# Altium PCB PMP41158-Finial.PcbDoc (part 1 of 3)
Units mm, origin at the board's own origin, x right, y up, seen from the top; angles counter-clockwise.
Board outline 125.73 x 87.63 mm, 6 copper layers (Top Layer, Layer 2, Layer 3, Layer 4, Layer 5, Bottom Layer), stack 1.999 mm thick; 200 components, 69 nets, 525 pads, 780 vias.
Unrouted connection lines stored in the file: 16.
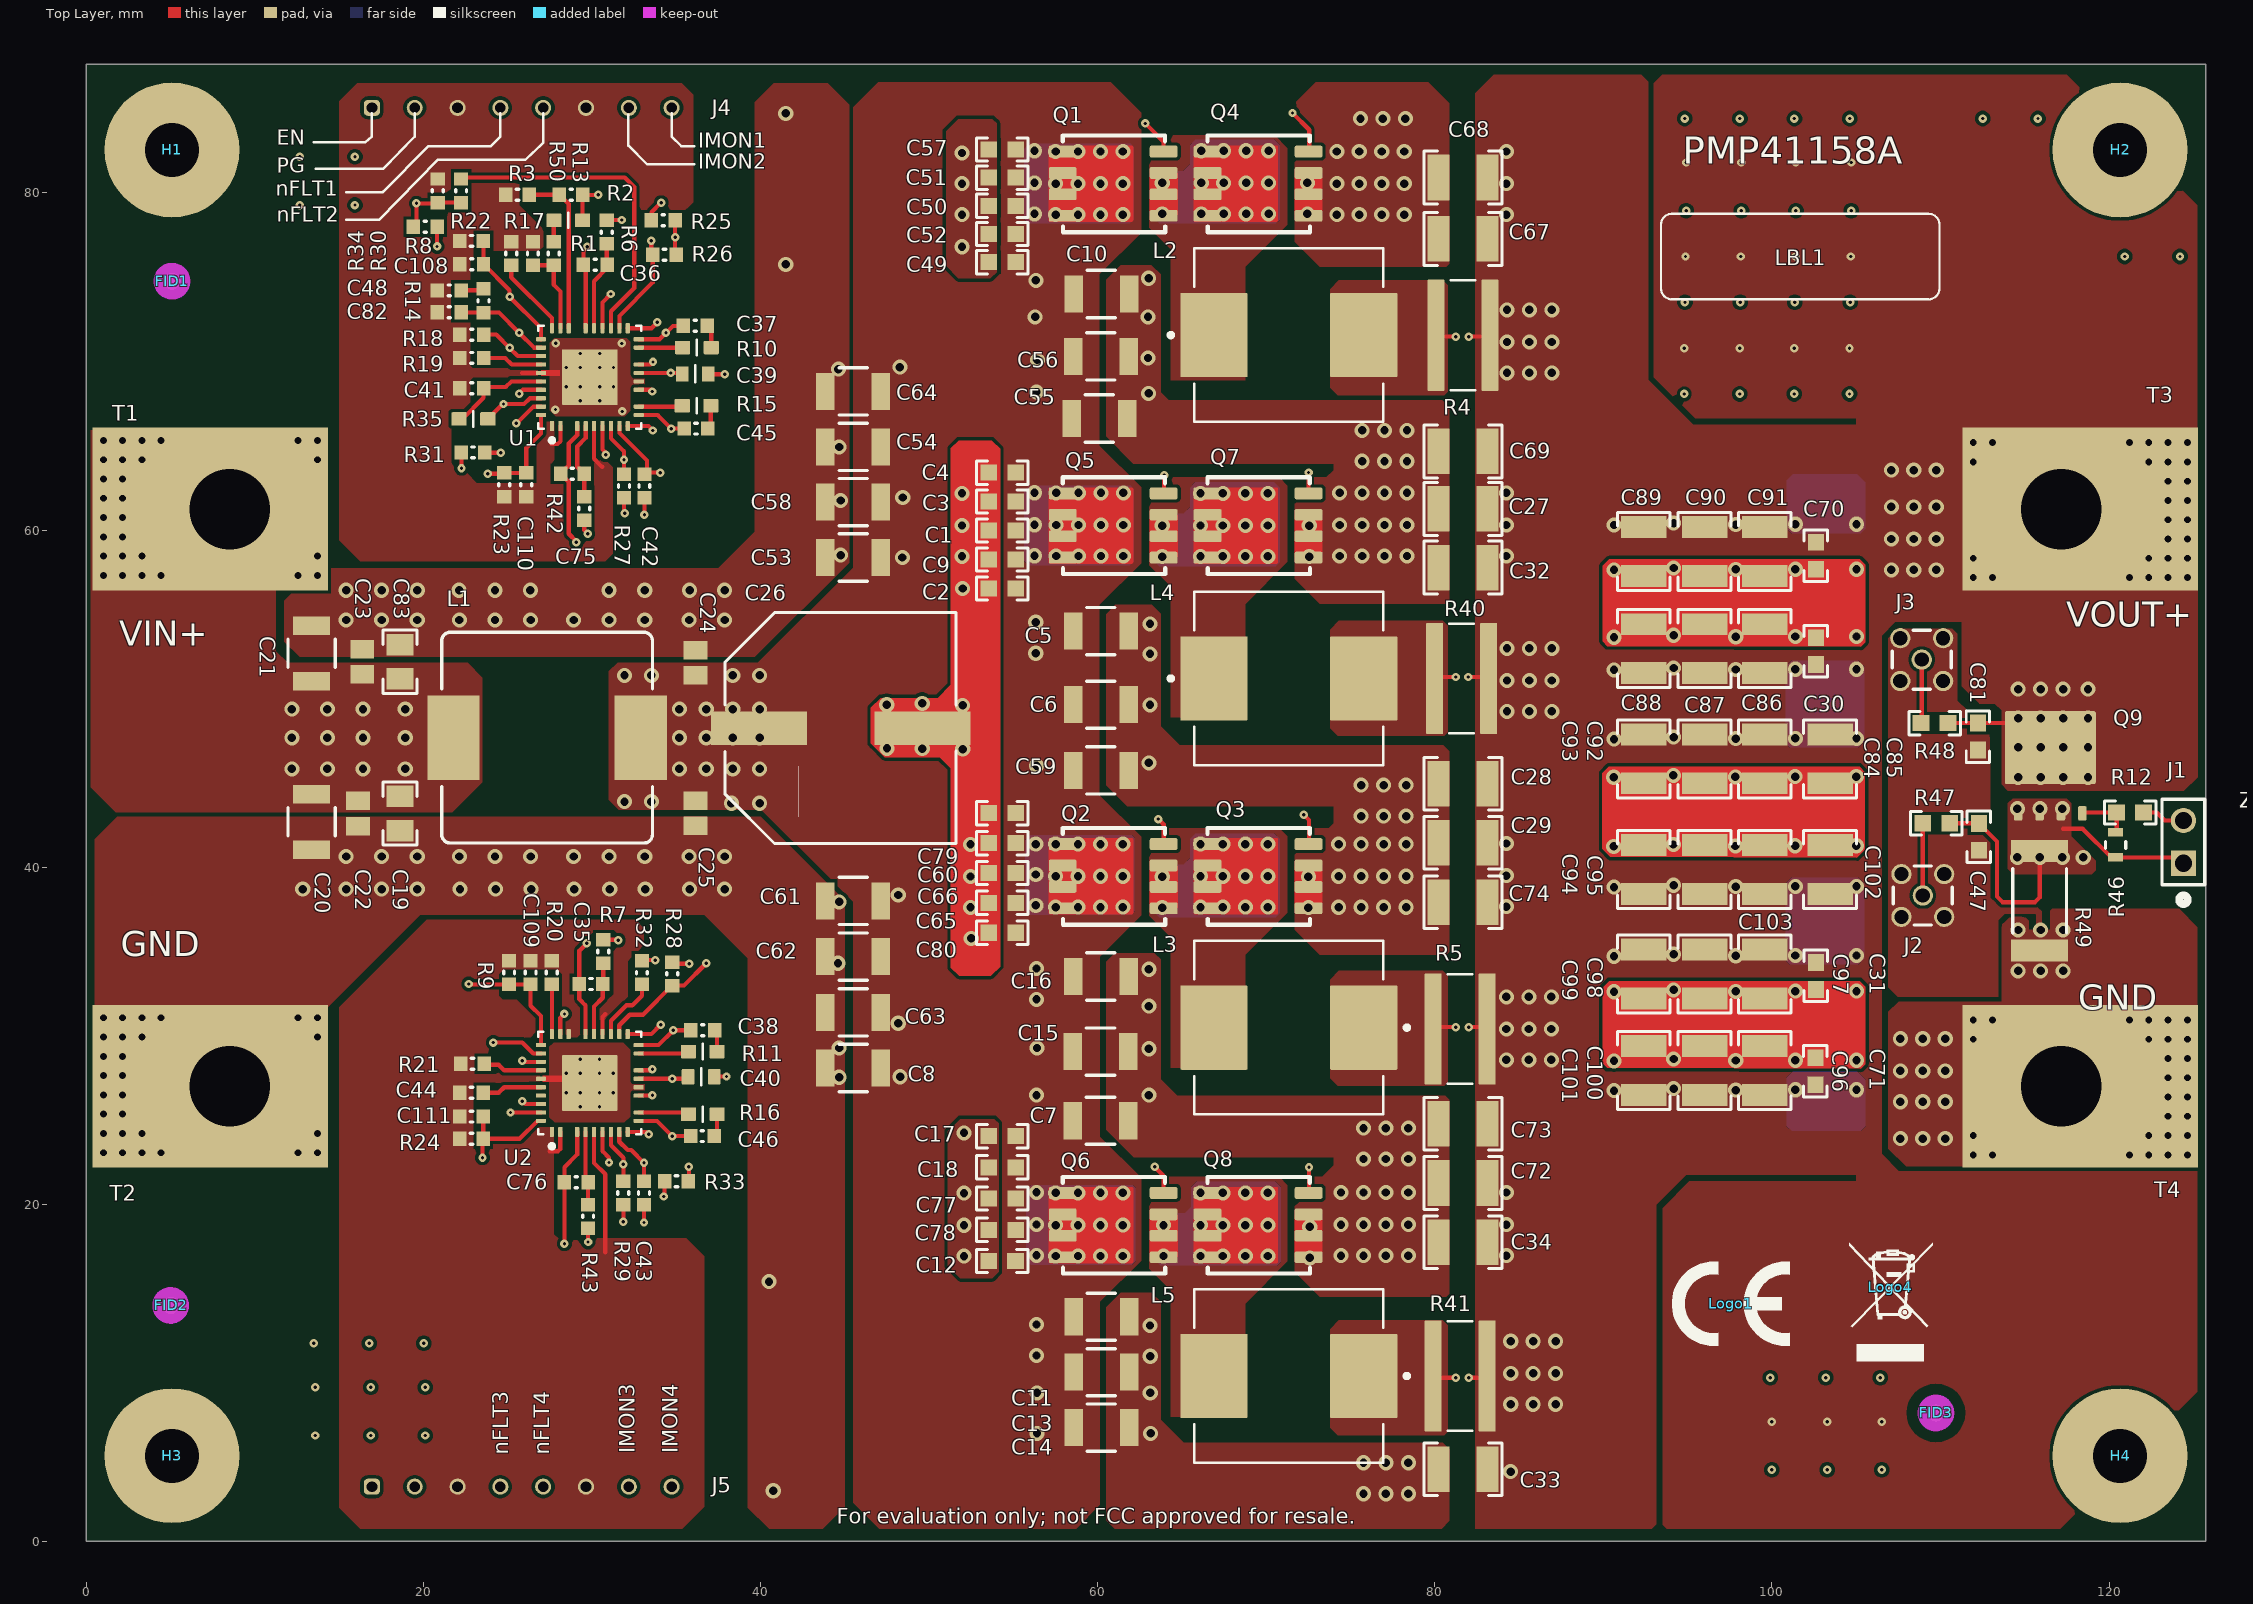
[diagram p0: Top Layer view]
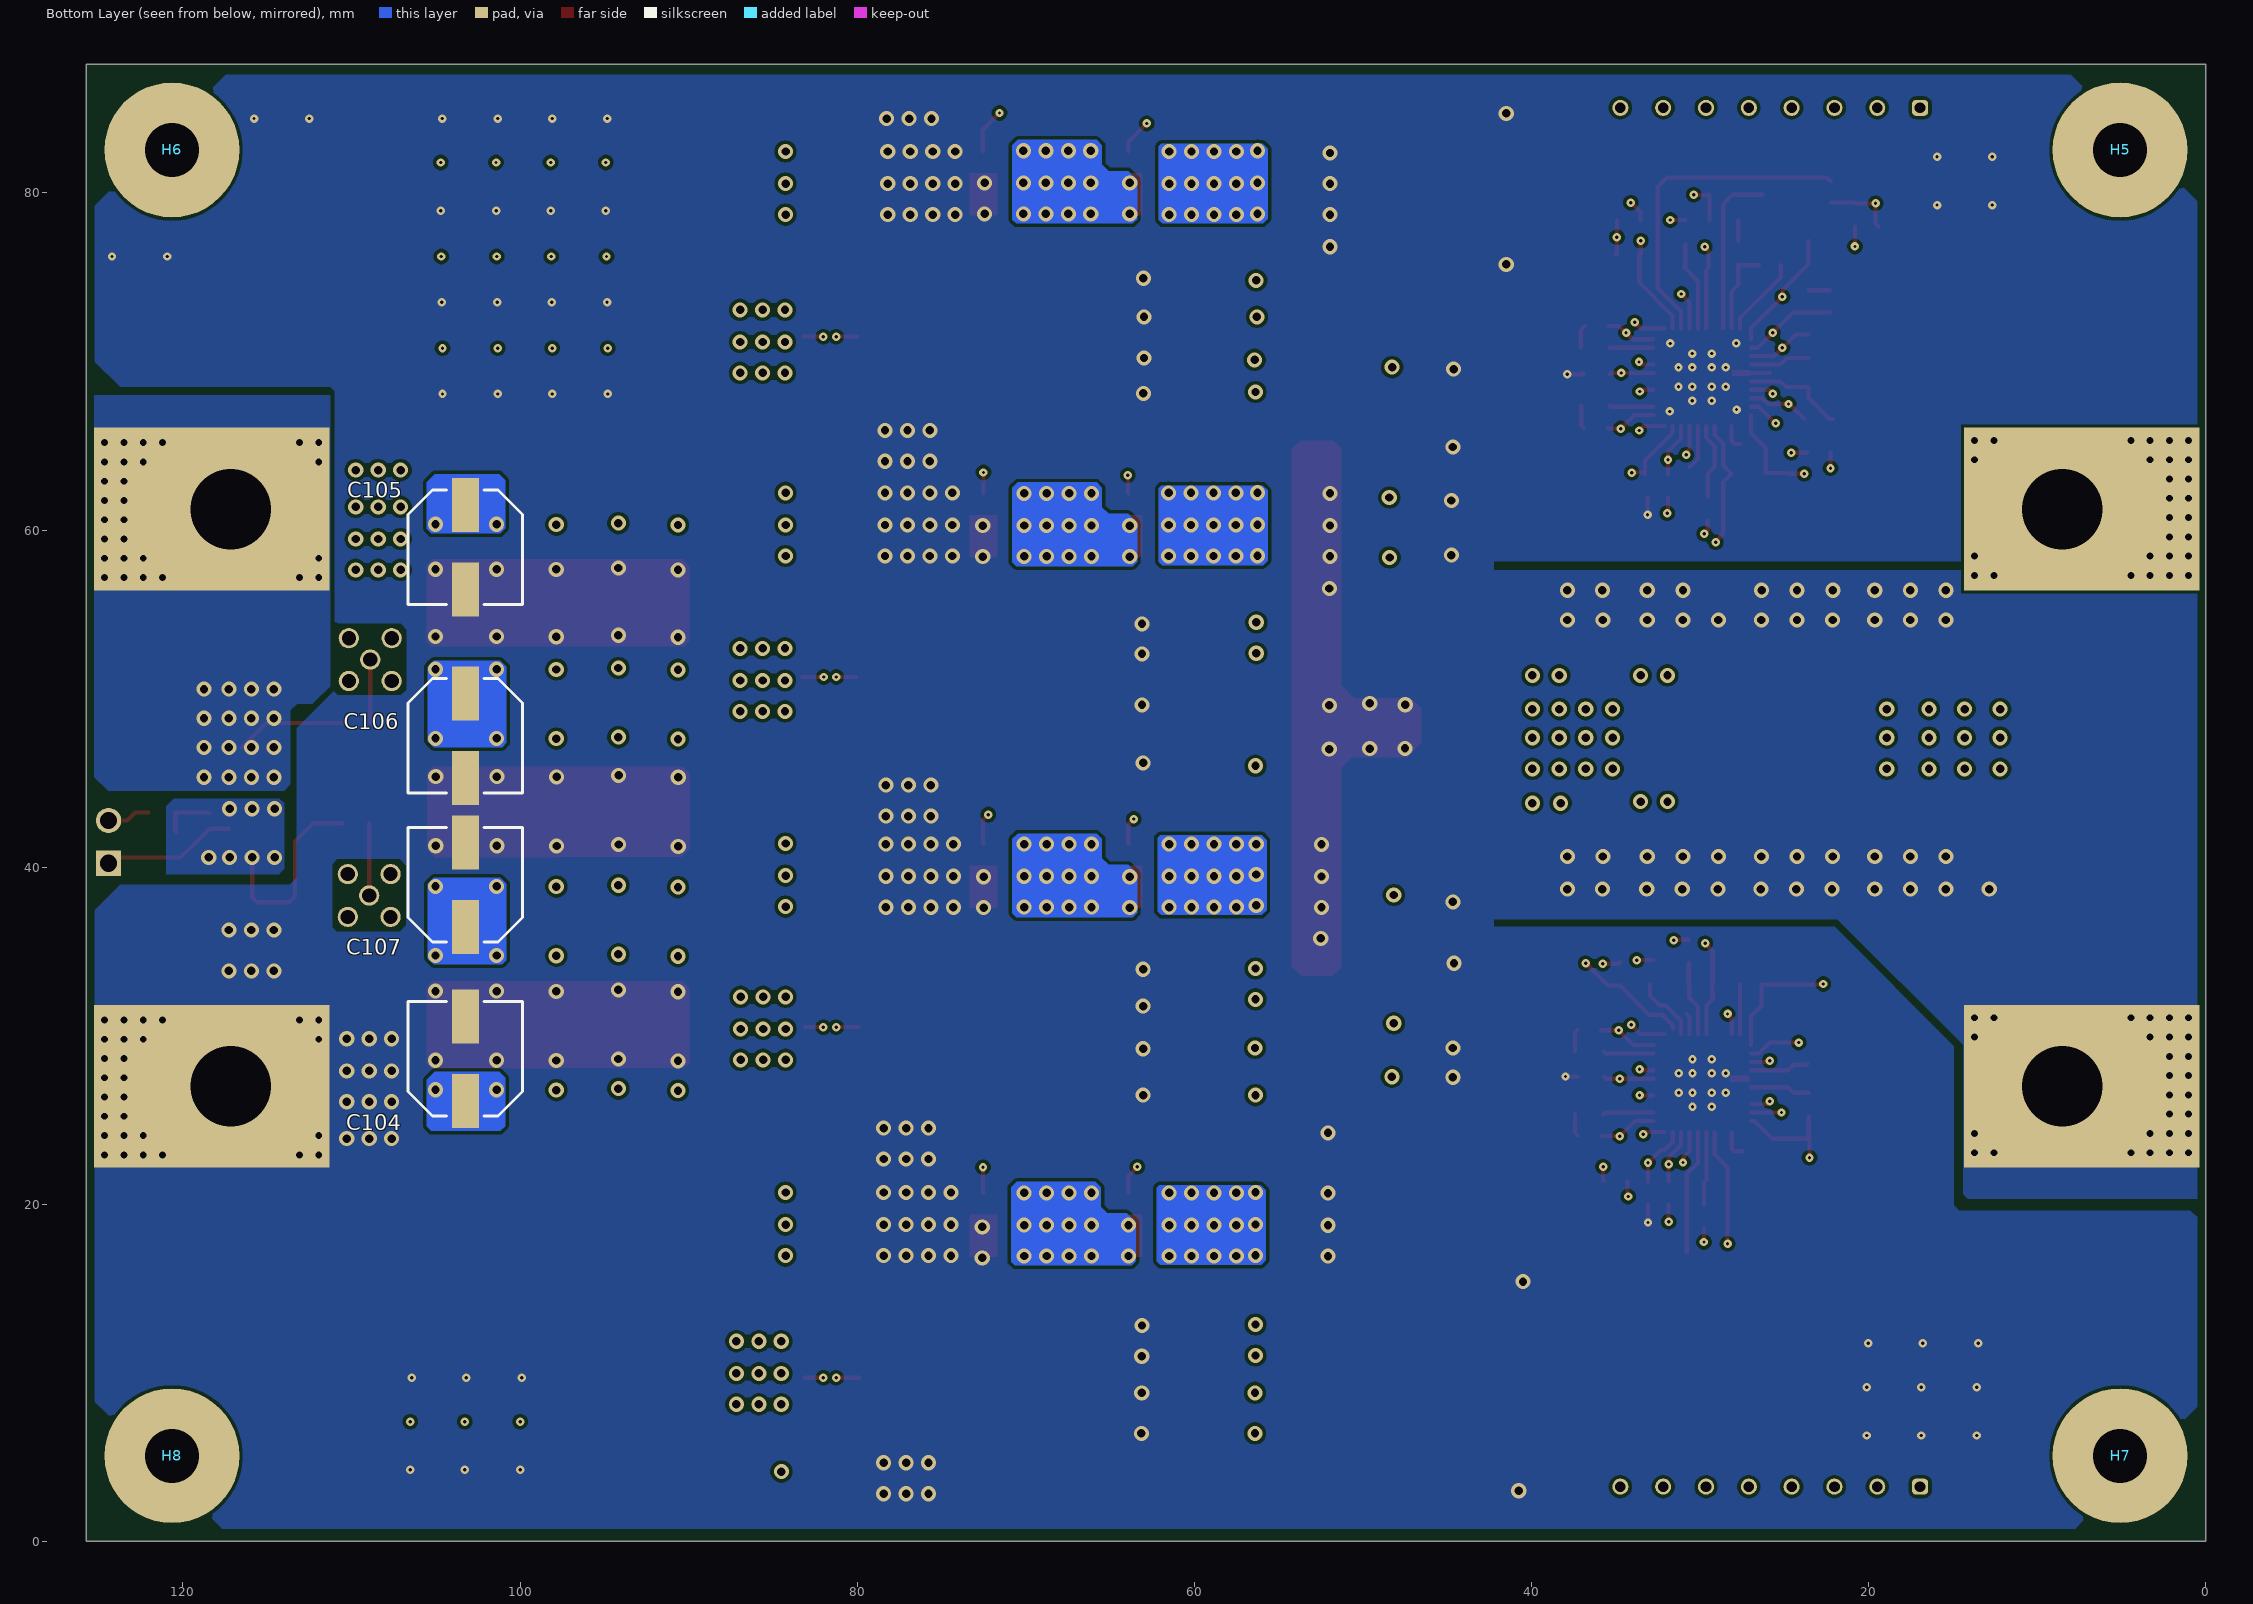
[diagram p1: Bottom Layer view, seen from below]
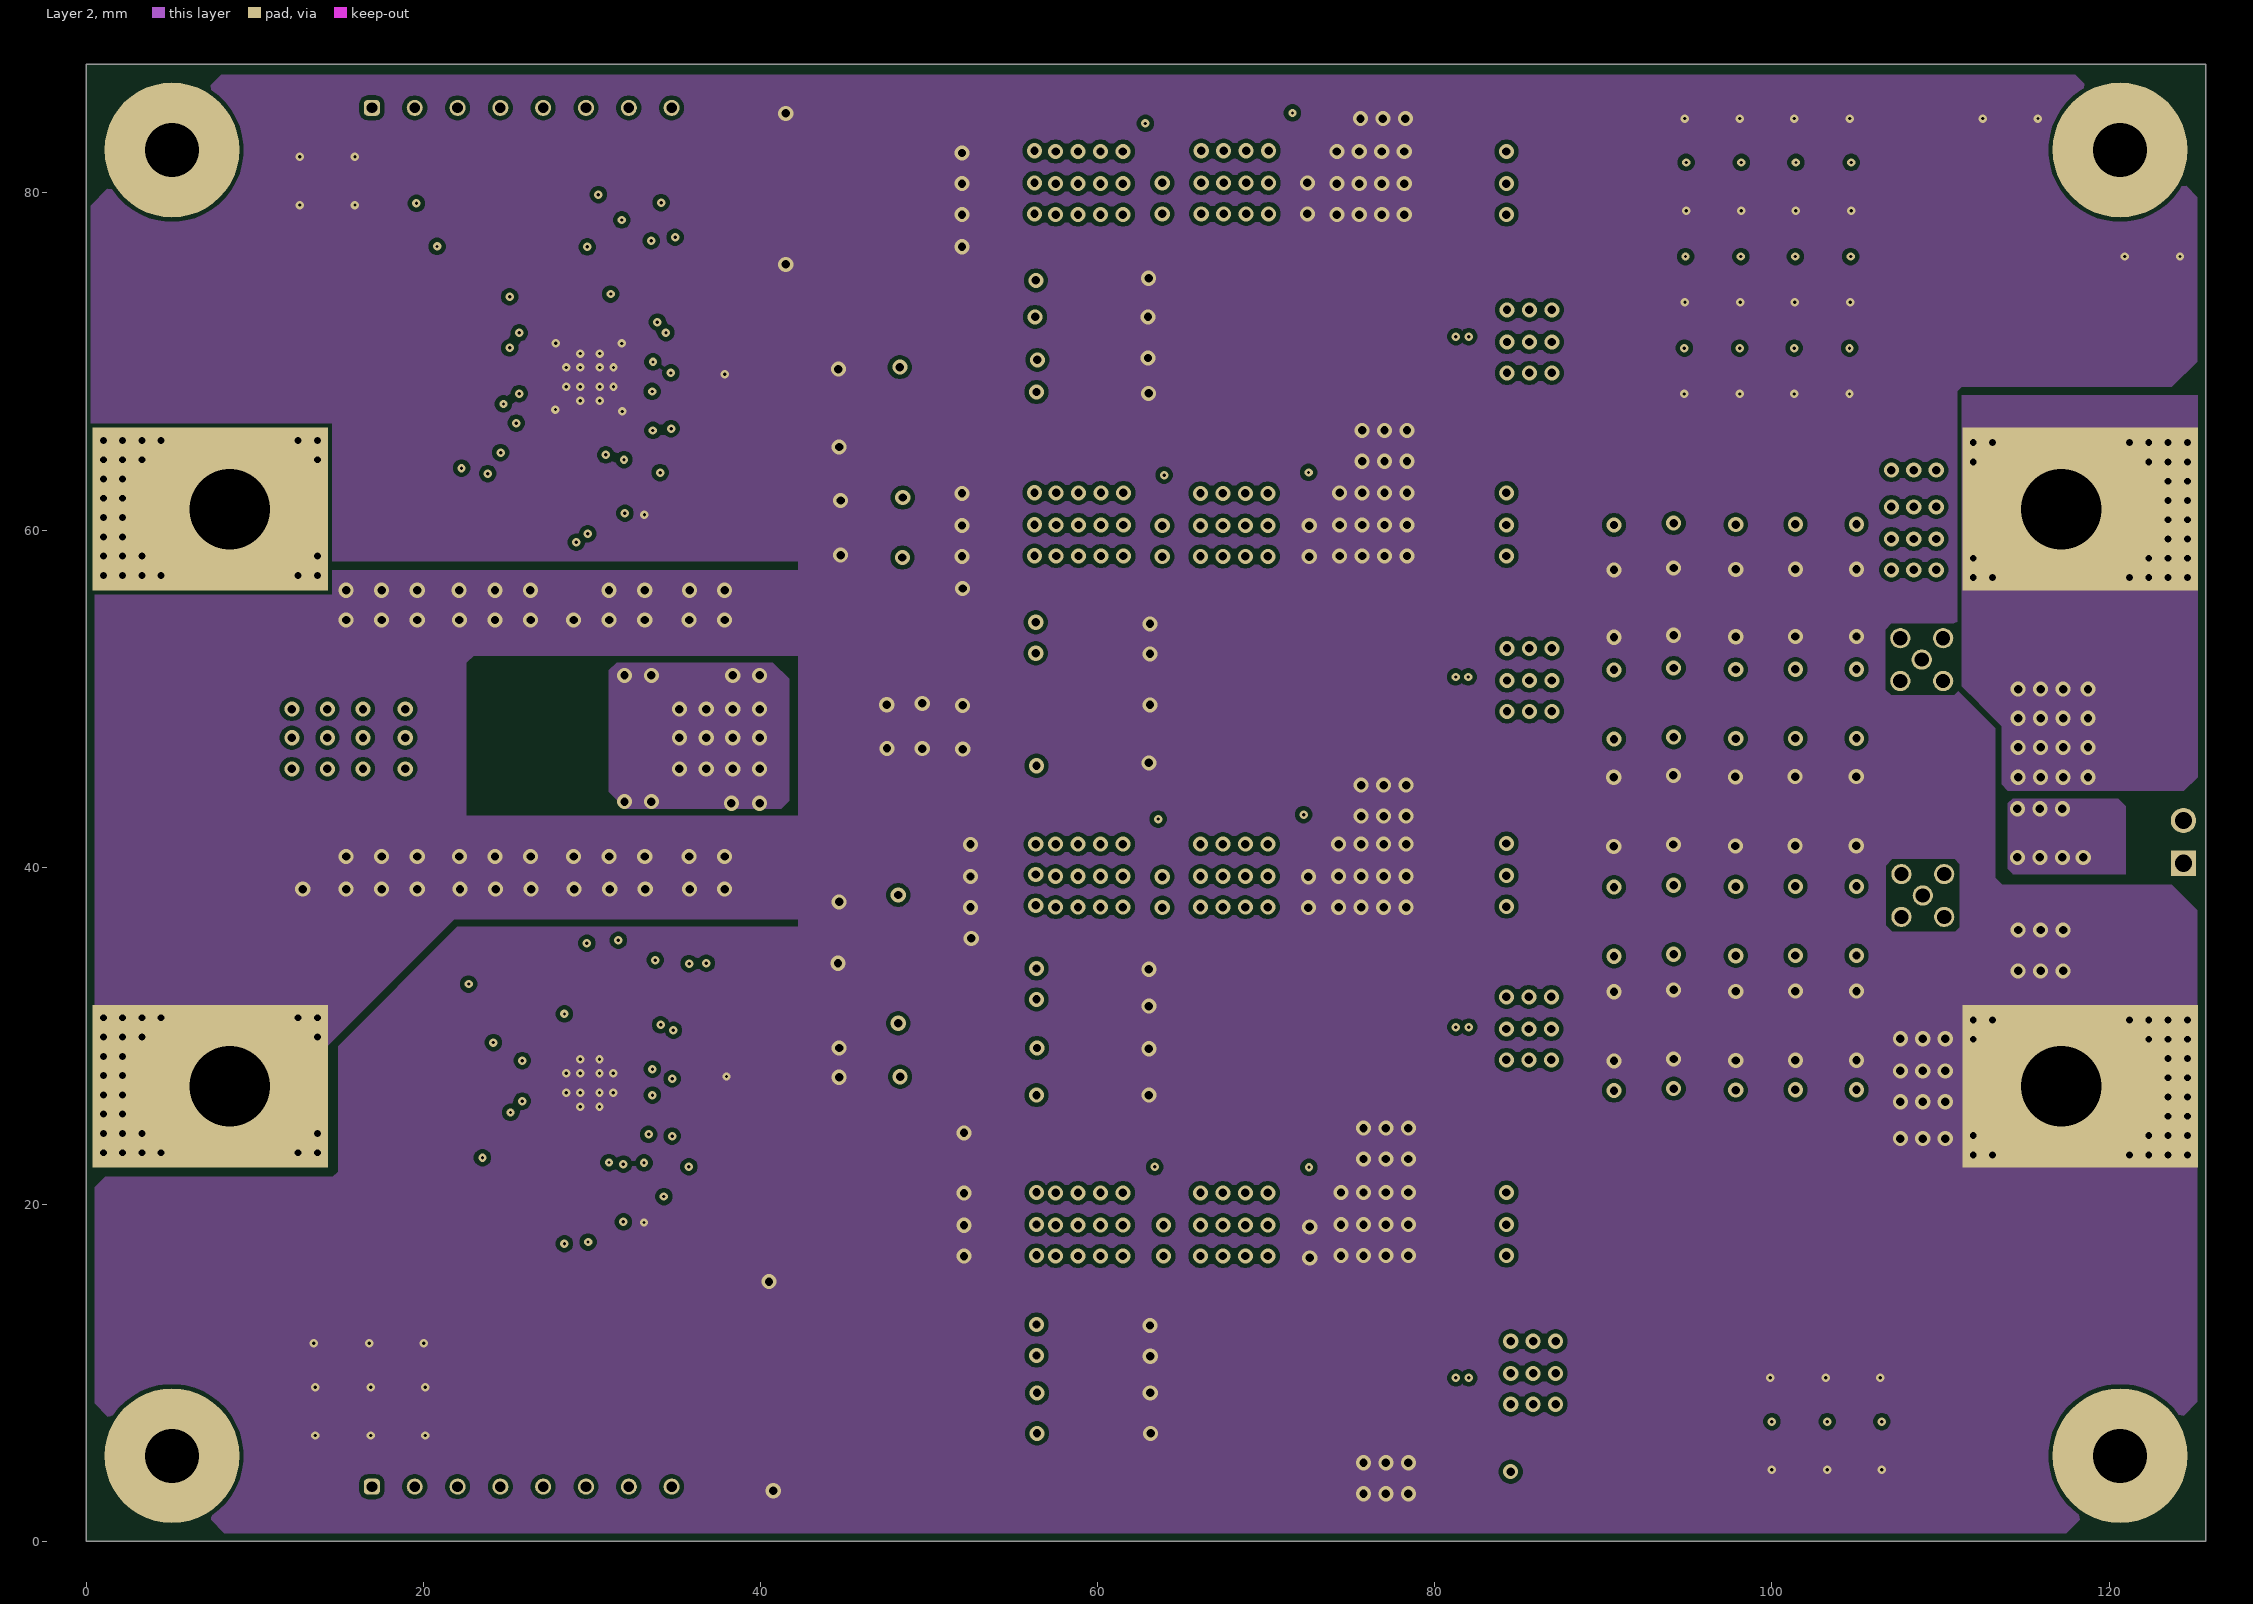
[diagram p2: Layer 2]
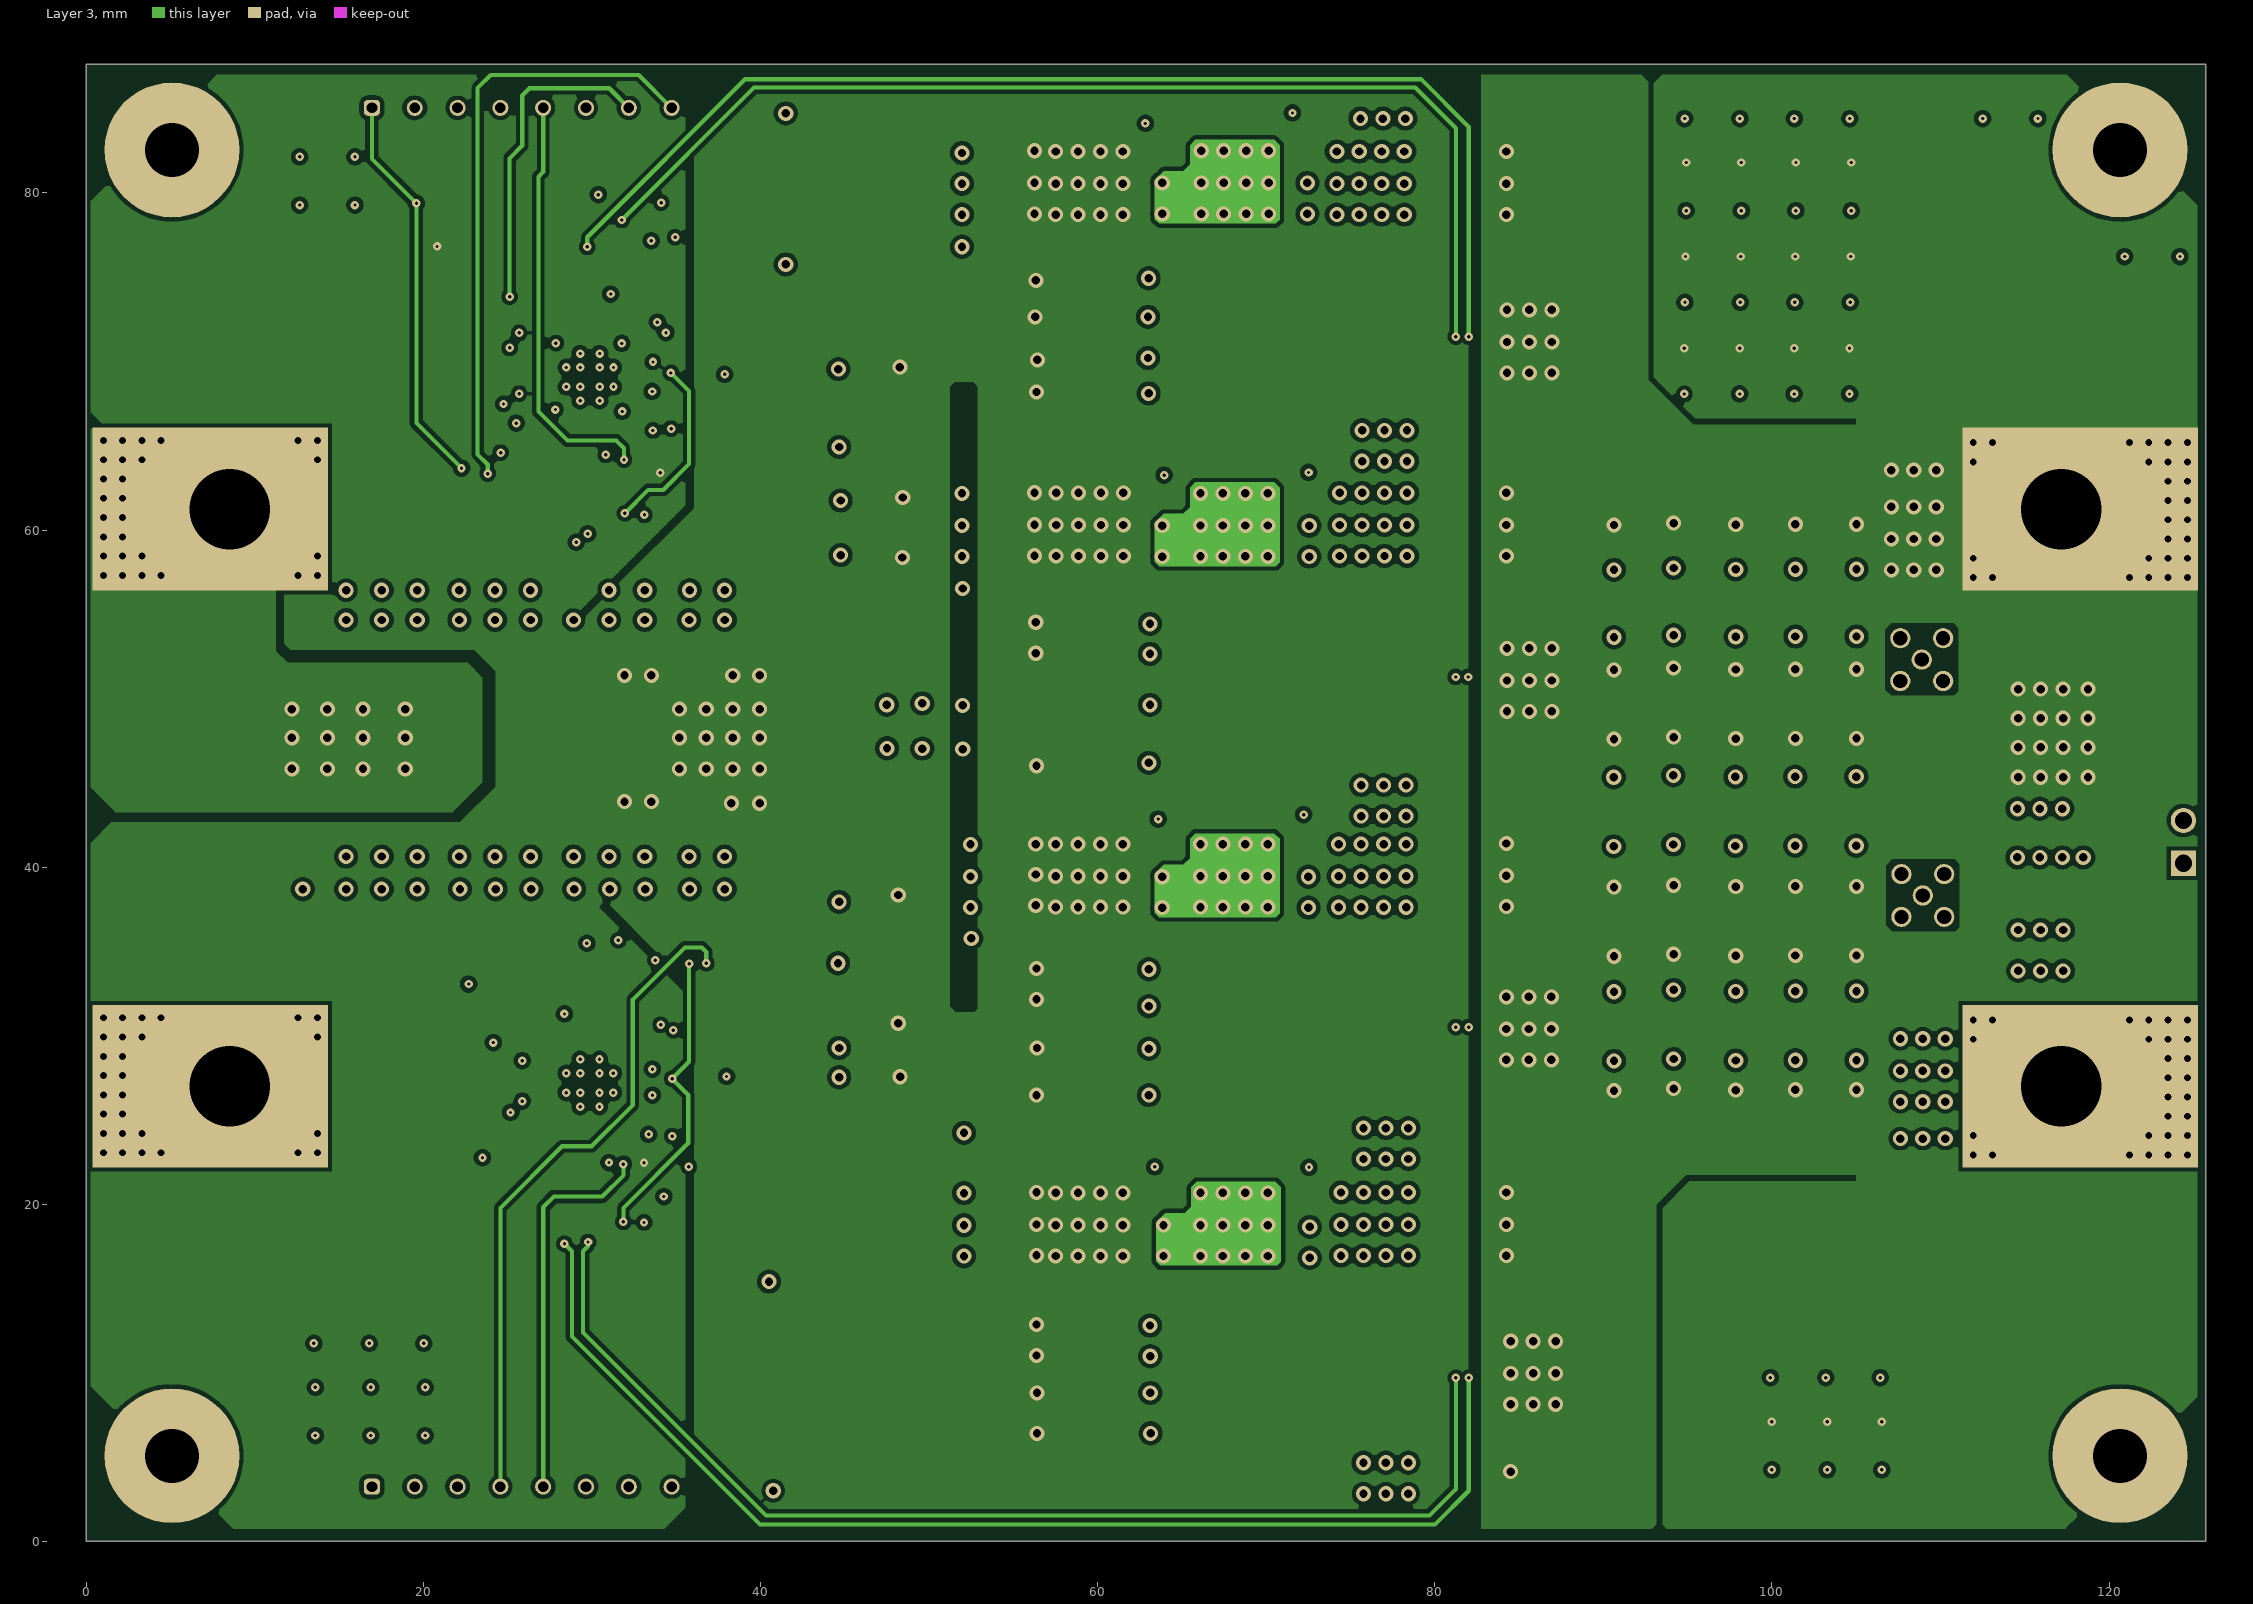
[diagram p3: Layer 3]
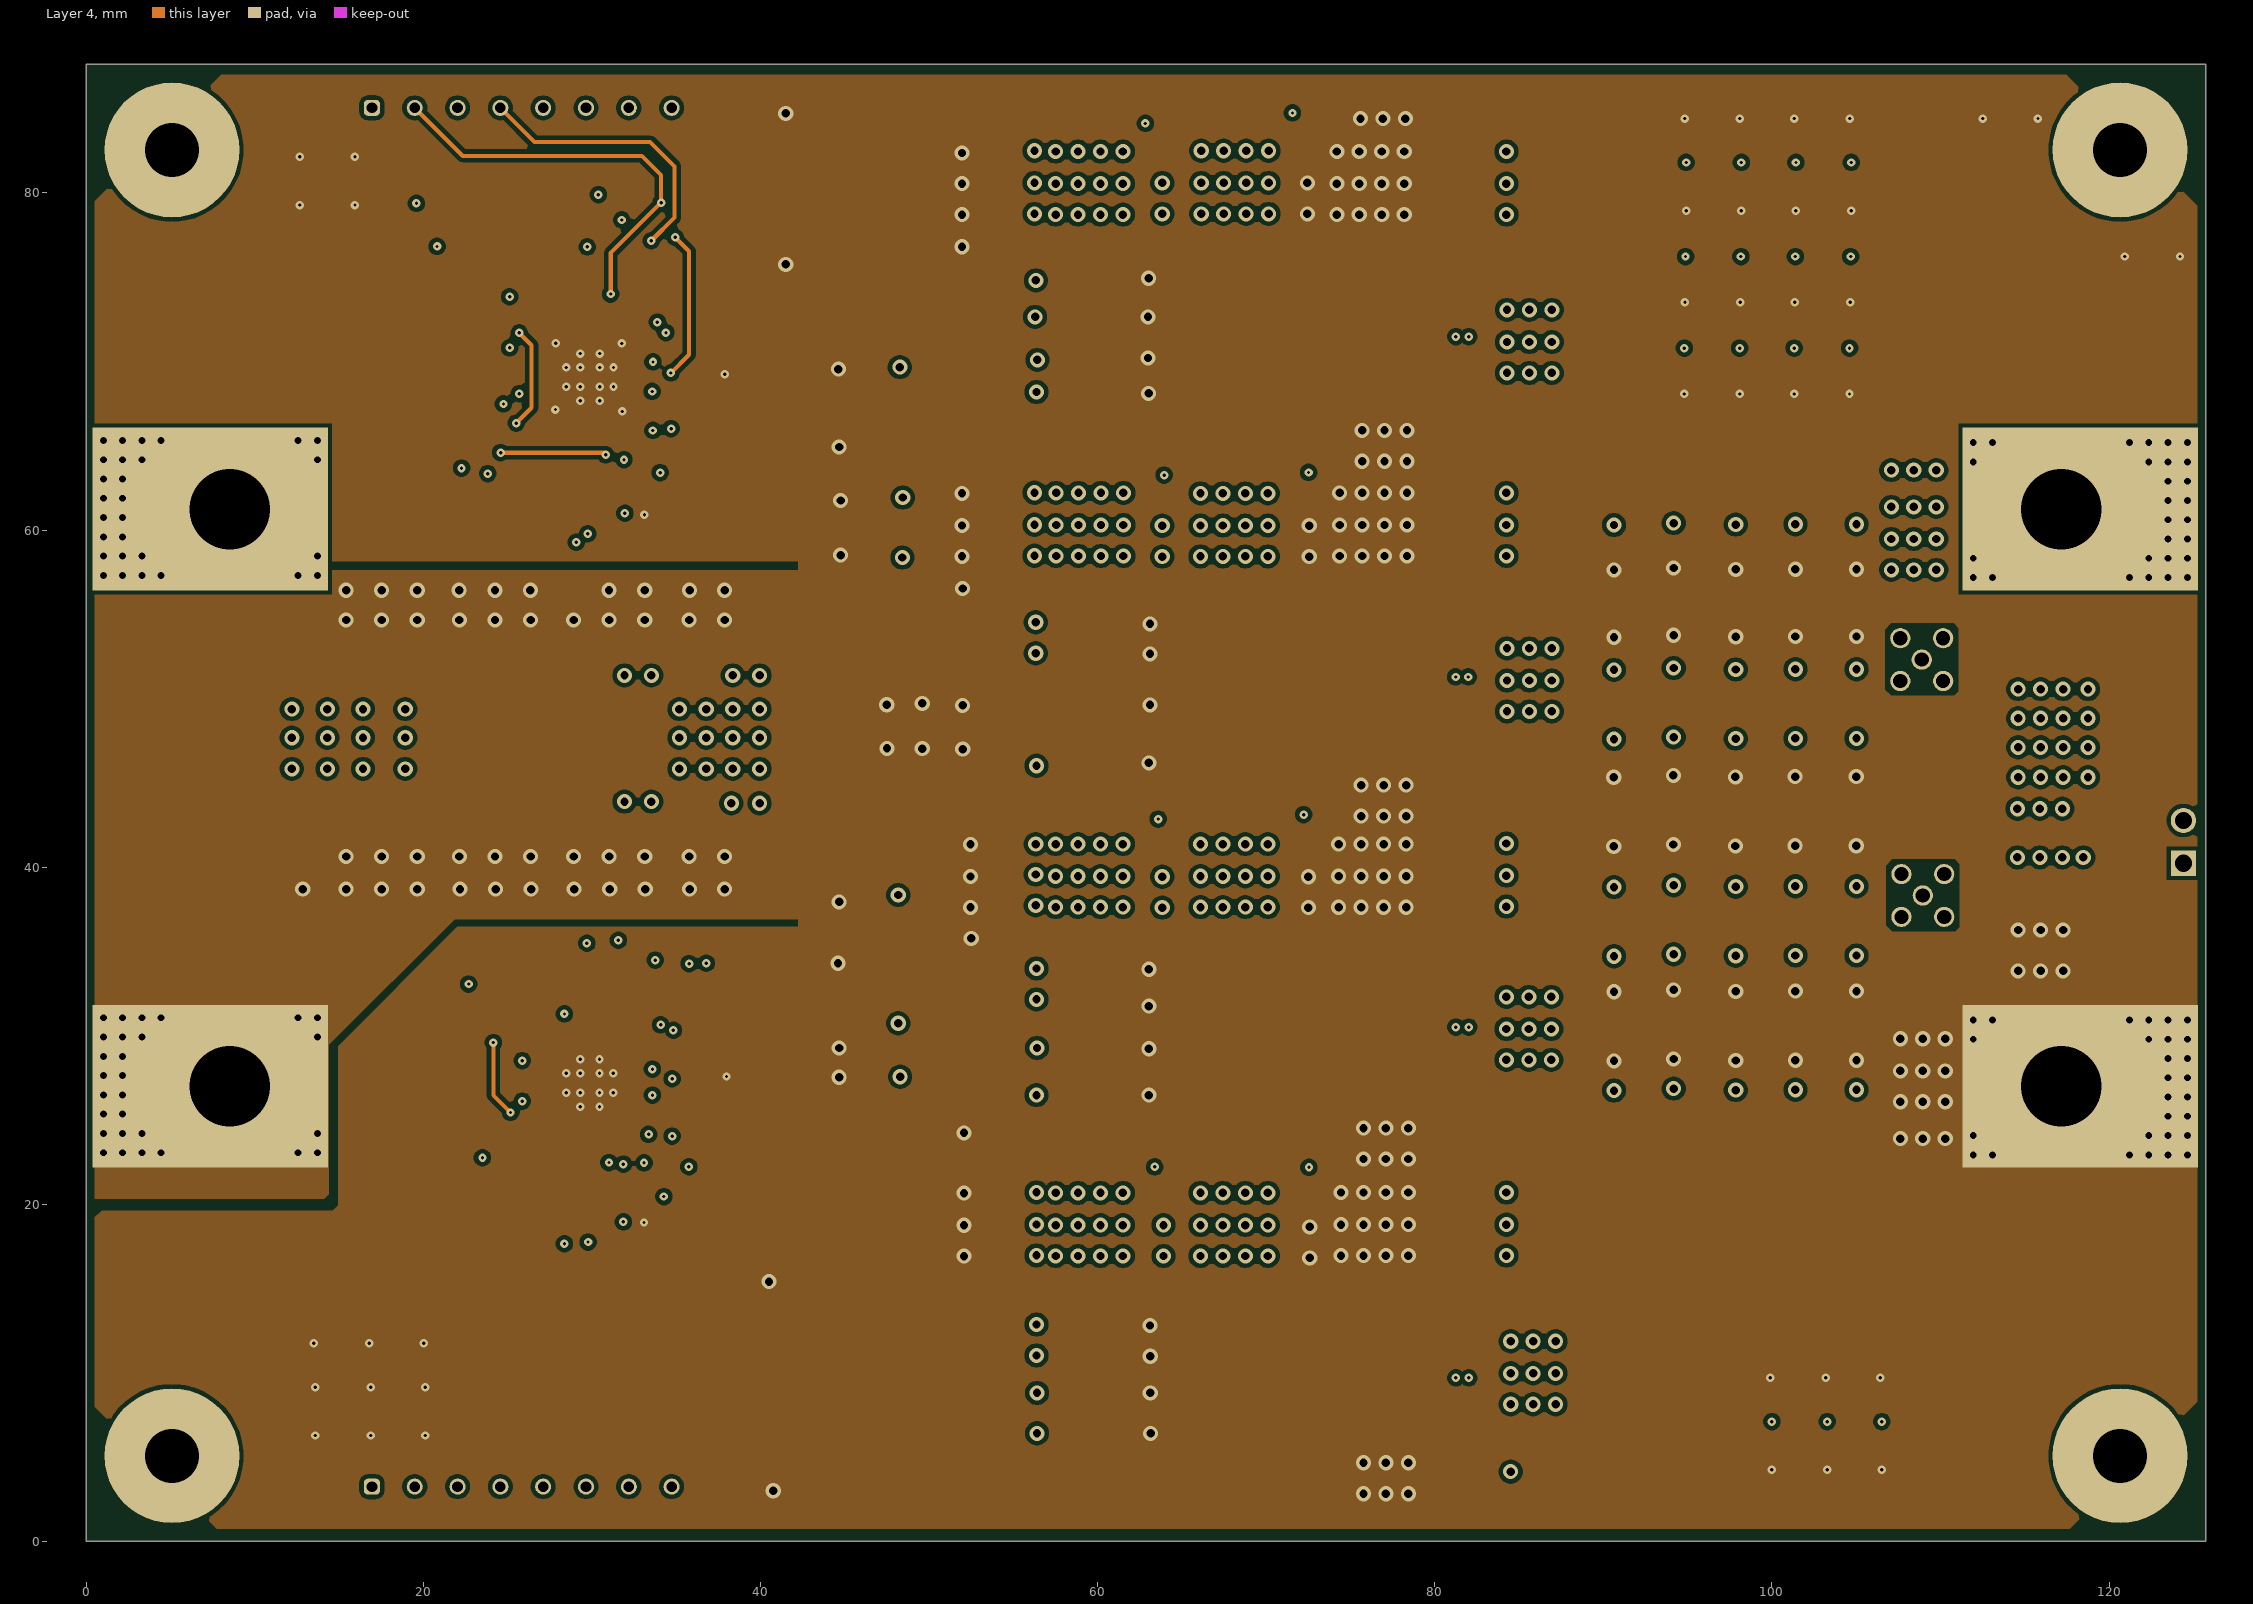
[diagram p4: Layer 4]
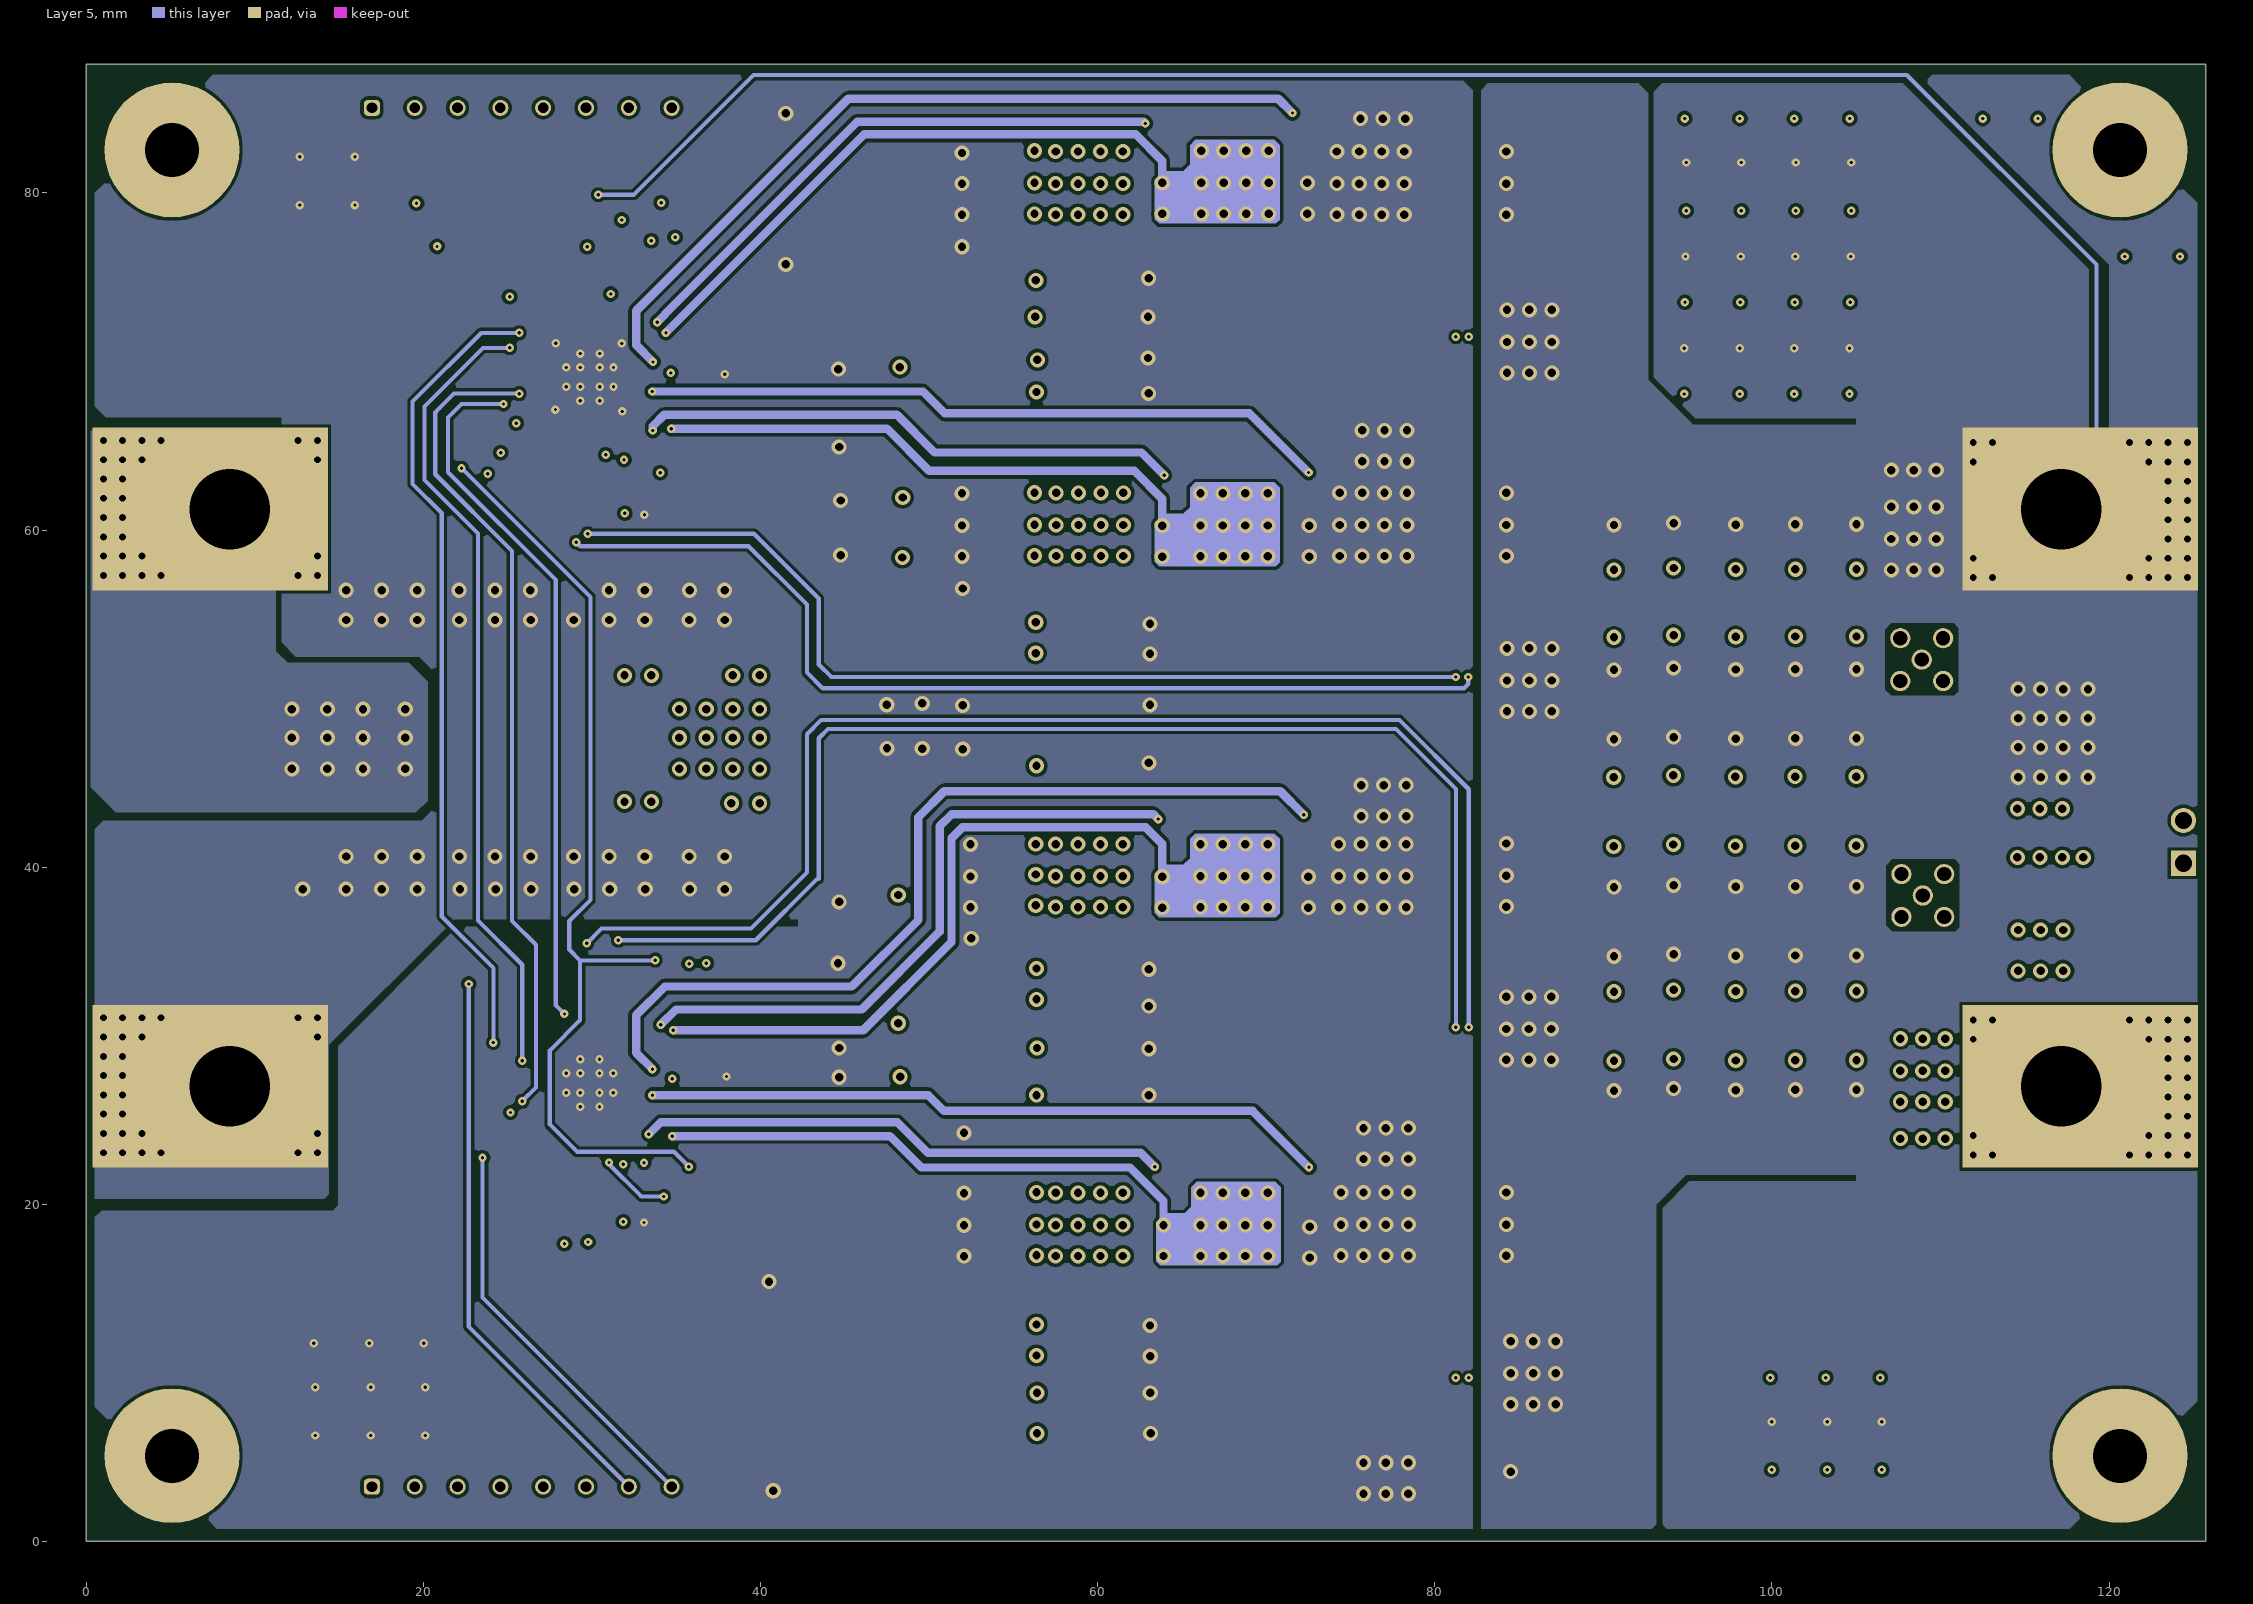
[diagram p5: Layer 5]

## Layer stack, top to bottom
Top Solder: solder mask 0.0102, Solder Resist, Dk 3.5
Top Layer: signal copper 0.0356
Dielectric 1: prepreg 0.0711, PP-006, Dk 4.1
Layer 2: signal copper 0.035
Dielectric 3: core 0.0711, PP-006, Dk 4.1
Layer 3: signal copper 0.035
Dielectric1: prepreg 1.5037, FR-4 High Tg, Dk 4.8
Layer 4: signal copper 0.035
Dielectric 4: core 0.0711, PP-006, Dk 4.1
Layer 5: signal copper 0.035
Dielectric 2: prepreg 0.0711, PP-006, Dk 4.1
Bottom Layer: signal copper 0.0356
Bottom Solder: solder mask 0.0102, Solder Resist, Dk 3.5

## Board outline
0,0 125.73,0 125.73,87.63 0,87.63

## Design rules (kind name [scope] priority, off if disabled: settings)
AcuteAngle [All] p1: minimum=4.50000000000000E+0001 checktracksonly=FALSE
AssemblyTestPointUsage [All] p1: valid=2
Clearance Clearance_BoardEdge_MountingHoles [OnCopper and InComponentClass('Mounting Holes') vs IsKeepOut] p1: gap=1.016 ignorepadtopadclearanceinfootprint=FALSE except(0: Arc-Hole Track-Hole SMDPad-Hole THPad-Hole Via-Hole Fill-Hole Poly-Hole Region-Hole Text-Hole)
Clearance Clearance_BoardEdge_Poly [OnCopper and InPoly vs IsKeepOut] p2: gap=0.635 ignorepadtopadclearanceinfootprint=FALSE except(0: Arc-Hole Track-Hole SMDPad-Hole THPad-Hole Via-Hole Fill-Hole Poly-Hole Region-Hole Text-Hole)
Clearance Clearance_BoardEdge [OnCopper and Not InComponentClass('Logo') and not InComponentClass('FiducialMark') and not InRegion(1000,500,4000,800) and Not IsKeepout vs IsKeepOut] p3: gap=0.127 ignorepadtopadclearanceinfootprint=FALSE except(0: Arc-Hole Track-Hole SMDPad-Hole THPad-Hole Via-Hole Fill-Hole Poly-Hole Region-Hole Text-Hole)
Clearance Clearance_Poly [InPolygon and ( OnLayer('Layer 1') or OnLayer('Layer 2') or OnLayer('Layer 3') or OnLayer('Layer 4') )] p4: gap=0.254 ignorepadtopadclearanceinfootprint=FALSE except(0: Arc-Hole Track-Hole SMDPad-Hole THPad-Hole Via-Hole Fill-Hole Poly-Hole Region-Hole Text-Hole)
Clearance [All] p5: gap=0.2 ignorepadtopadclearanceinfootprint=FALSE except(0: Arc-Hole Track-Hole SMDPad-Hole THPad-Hole Via-Hole Fill-Hole Poly-Hole Region-Hole Text-Hole)
ComponentClearance ComponentClearance_Logo [All] p1: gap=0.254 collisioncheckmode=3 verticalgap=0.254 showdistances=TRUE
ComponentClearance ComponentClearance_ScrewToNut [(HasFootprint('NY PMS 440 0025 PH')) vs (HasFootprint('Keystone_1902C'))] p2: gap=0.127 collisioncheckmode=3 verticalgap=0.254 showdistances=FALSE
ComponentClearance ComponentClearance_MountingHoles [InComponentClass('Mounting Holes')] p3: gap=0.254 collisioncheckmode=3 verticalgap=2540 showdistances=FALSE
ComponentClearance ComponentClearance_SmallPassives [HasFootprint('0201*') or HasFootprint('0402*') or HasFootprint('0508') or HasFootprint('0603*') or HasFootprint('0612') or HasFootprint('0805*') or HasFootprint('0815*') or HasFootprint('0830*') or HasFootprint('1206*') or HasFootprint('1210*') or HasFootprint('1808*') or HasFootprint('1812*') or HasFootprint('1825*') or HasFootprint('2010*') or HasFootprint('2220*') or HasFootprint('2225*') or HasFootprint('2512*') or HasFootprint('2728*') or HasFootprint('3518*') vs HasFootprint('0201*') or HasFootprint('0402*') or HasFootprint('0508') or HasFootprint('0603*') or HasFootprint('0612') or HasFootprint('0805*') or HasFootprint('0815*') or HasFootprint('0830*') or HasFootprint('1206*') or HasFootprint('1210*') or HasFootprint('1808*') or HasFootprint('1812*') or HasFootprint('1825*') or HasFootprint('2010*') or HasFootprint('2220*') or HasFootprint('2225*') or HasFootprint('2512*') or HasFootprint('2728*') or HasFootprint('3518*')] p4: gap=0.254 collisioncheckmode=3 verticalgap=0.254 showdistances=FALSE
ComponentClearance ComponentClearance_THtoSMT [IsThruComponent vs IsSMTComponent] p5: gap=0.254 collisioncheckmode=3 verticalgap=2540 showdistances=FALSE
ComponentClearance ComponentClearance_THtoTH [IsThruComponent vs IsThruComponent] p6: gap=0.254 collisioncheckmode=3 verticalgap=2540 showdistances=FALSE
ComponentClearance [All] p7: gap=0.254 collisioncheckmode=3 verticalgap=0.254 showdistances=FALSE
DiffPairsRouting [All] p1: maxlimit=2.54 minlimit=0.254 mostfreqgap=0.254 toplayer_minwidth=0.381 toplayer_maxwidth=0.381 toplayer_prefwidth=0.381 midlayer1_minwidth=0.381 midlayer1_maxwidth=0.381 midlayer1_prefwidth=0.381 midlayer2_minwidth=0.381 midlayer2_maxwidth=0.381 midlayer2_prefwidth=0.381 midlayer3_minwidth=0.381 midlayer3_maxwidth=0.381 midlayer3_prefwidth=0.381 midlayer4_minwidth=0.381 midlayer4_maxwidth=0.381 midlayer4_prefwidth=0.381 bottomlayer_minwidth=0.381 bottomlayer_maxwidth=0.381 bottomlayer_prefwidth=0.381 maxuncoupledlength=25.4
FabricationTestPointUsage TestPointUsage [All] p1: valid=2 allowmultiple=FALSE
FabricationTestpoint Testpoint [All] p1: side=3 testpointundercomponent=TRUE minsize=1.016 maxsize=2.54 preferedsize=1.524 minholesize=0 maxholesize=1.016 preferedholesize=0.813 testpointgrid=0.025 allowsidetop=TRUE allowsidebottom=TRUE usegrid=TRUE gridtolerance=0
FanoutControl Fanout_LCC [IsLCC] p1: bgadir=Out bgaviamode=Centered fanoutstyle=Auto fanoutdirection=Alternating viagrid=0.025 // Fanout_LCC (Default Rule)
FanoutControl Fanout_BGA [IsBGA] p2: bgadir=Out bgaviamode=Centered fanoutstyle=Auto fanoutdirection=Alternating viagrid=0.025 // Fanout_BGA (Default Rule)
FanoutControl Fanout_Default [All] p4: bgadir=Out bgaviamode=Centered fanoutstyle=Auto fanoutdirection=Alternating viagrid=0.025 // Fanout_Default (Default Rule)
FanoutControl Fanout_Small [(CompPinCount < 5)] p5: bgadir=Out bgaviamode=Centered fanoutstyle=Auto fanoutdirection=OutThenIn viagrid=0.025 // Fanout_Small (Default Rule)
HoleSize [All] p1: absolutevalues=TRUE maxlimit=6.375 minlimit=0.152 maxpercent=80.000 minpercent=20.000
MinimumAnnularRing [All] p1: minimumring=0.076
MinimumSolderMaskSliver MinimumSolderMaskSliver_Logo [InComponentClass('Logo') vs InComponentClass('Logo')] p1: minsoldermaskwidth=0.018
MinimumSolderMaskSliver [All] p2: minsoldermaskwidth=0
PlaneConnect [All] p1: planeconnectstyle=Direct reliefexpansion=0.254 reliefentries=4 reliefconductorwidth=0.254 reliefairgap=0.254
PolygonConnect [All] p1: connectstyle=Direct reliefconductorwidth=0.254 reliefentries=4 polygonreliefangle="90 Angle" airgapwidth=0.254
RoutingCorners [All] p1: cornerstyle=45-Degree minsetback=0.254 maxsetback=2.54
RoutingVias [All] p1: holewidth=0.406 width=0.864 viastyle="Through Hole" minholewidth=0.2 minwidth=0.406 maxholewidth=1.016 maxwidth=1.651
SMDToCorner [All] p1: distance=0
SilkToBoardRegionClearance [Not ((IsComment or IsDesignator) And (Hide <> 'False')) and not InRegion(1000,500,4000,800)] p1:
SilkToSilkClearance [All] p1: silktosilkclearance=0
SilkToSolderMaskClearance SilkscreenOverComponentPads [IsPad] p1: minsilkscreentomaskgap=0 clearancetoexposedcopper=TRUE
SolderMaskExpansion [All] p1: expansion=0.076 istentingtop=FALSE
Width [All] p1: maxlimit=2.54 minlimit=0.152 preferedwidth=0.254 checkconnectedcopper=TRUE
14 further rules are at their usual default settings.

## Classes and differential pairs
component class Header: J1 J4 J5
component class PMP41158: C1 C2 C3 C4 C5 C6 C7 C8 C9 C10 C11 C12 C13 C15 C16 C17 C18 C19 C20 C21 C22 C23 C24 C25 C26 C27 C28 C29 C30 C31 C32 C33 C34 C35 C36 C37 C38 C39 C40 C41 C42 C43 C44 C45 C46 C47 C48 C49 C50 C51 C52 C53 C54 C55 C56 C57 C58 C59 C60 C61 C62 C63 C64 C65 C66 C67 C68 C69 C70 C71 C72 C73 C74 C75 C76 C77 C78 C79 C80 C81 C82 C83 C84 C85 C86 C87 C88 C89 C90 C91 C92 C93 C94 C95 C96 C97 C98 C99 C100 C101 C102 C103 C104 C105 C106 C107 C108 C109 C110 C111 J1 J2 J3 J4 J5 L1 L2 L3 L4 L5 Q1 Q2 Q3 Q4 Q5 Q6 Q7 Q8 Q9 R1 R2 R3 R4 R5 R6 R7 R8 R9 R10 R11 R12 R13 R14 R15 R16 R17 R18 R19 R20 R21 R22 R23 R24 R25 R26 R27 R28 R29 R30 R31 R32 R33 R34 R35 R40 R41 R42 R43 R46 R47 R48 R49 R50 T1 T2 T3 T4 U1 U2
component class "Mounting Holes": H1 H2 H3 H4
component class Logo: Logo2
component class PMP41158_Hardware: FID1 FID2 FID3 H1 H2 H3 H4 H5 H6 H7 H8 LBL1 Logo1 Logo2 Logo3 Logo4 ZZ1 ZZ2 ZZ3 ZZ4
component class FiducialMark: FID1 FID2 FID3
component class AssemblyNote: ZZ1 ZZ2 ZZ3 ZZ4
component class Label: LBL1

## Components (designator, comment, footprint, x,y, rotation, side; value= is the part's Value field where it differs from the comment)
C1 "CGA3E2X7R2A103K080AA" 0603 54.338,59.971 r180 top value=0.01uF
C2 "CGA3E2X7R2A103K080AA" 0603 54.338,56.534 r180 top value=0.01uF
C3 "CGA3E2X7R2A103K080AA" 0603 54.338,61.69 r180 top value=0.01uF
C4 "CGA3E2X7R2A103K080AA" 0603 54.338,63.409 r180 top value=0.01uF
C5 "CGA6P3X7S1H106K250AE" 1210_280 60.194,54.01 r0 top value=10uF
C6 "CGA6P3X7S1H106K250AE" 1210_280 60.194,49.642 r0 top value=10uF
C7 "CGA6P3X7S1H106K250AE" 1210_280 60.165,24.956 r0 top value=10uF
C8 "CGA6P3X7S1H106K250AE" 1210_280 45.491,28.088 r180 top value=10uF
C9 "CGA3E2X7R2A103K080AA" 0603 54.338,58.253 r180 top value=0.01uF
C10 "CGA6P3X7S1H106K250AE" 1210_280 60.22,74.004 r0 top value=10uF
C11 "CGA6P3X7S1H106K250AE" 1210_280 60.22,13.331 r0 top value=10uF
C12 "CGA3E2X7R2A103K080AA" 0603 54.333,16.635 r180 top value=0.01uF
C13 "CGA6P3X7S1H106K250AE" 1210_280 60.22,10.041 r0 top value=10uF
C14 "CGA6P3X7S1H106K250AE" 1210_280 60.22,6.75 r0 top value=10uF
C15 "CGA6P3X7S1H106K250AE" 1210_280 60.165,29.064 r0 top value=10uF
C16 "CGA6P3X7S1H106K250AE" 1210_280 60.194,33.517 r0 top value=10uF
C17 "CGA3E2X7R2A103K080AA" 0603 54.338,24.046 r180 top value=0.01uF
C18 "CGA3E2X7R2A103K080AA" 0603 54.338,22.193 r180 top value=0.01uF
C19 "GCM21BR72A104KA37L" 0805_HV 18.613,43.184 r270 top value=0.1uF
C20 "CGA6P3X7S1H106K250AE" 1210_280 13.363,42.684 r270 top value=10uF
C21 "CGA6P3X7S1H106K250AE" 1210_280 13.363,52.684 r90 top value=10uF
C22 "CGA4J3X7R1H225K125AE" 0805L 16.113,43.184 r270 top value=2.2uF
C23 "CGA4J3X7R1H225K125AE" 0805L 16.363,52.184 r90 top value=2.2uF
C24 "CGA4J3X7R1H225K125AE" 0805L 36.139,52.128 r90 top value=2.2uF
C25 "CGA4J3X7R1H225K125AE" 0805L 36.139,43.203 r270 top value=2.2uF
C26 "EEV-FK1H331Q" SM_RADIAL_H13 44.75,48.252 r0 top value=330uF
C27 "GCM32EC71A476KE02K" 1210_270 81.677,61.255 r180 top value=47uF
C28 "GCM32EC71A476KE02K" 1210_270 81.677,44.953 r180 top value=47uF
C29 "GCM32EC71A476KE02K" 1210_270 81.677,41.453 r180 top value=47uF
C30 "GCM188R71E104KA57D" 0603 102.606,52.816 r90 top value=0.1uF
C31 "GCM188R71E104KA57D" 0603 102.606,33.553 r270 top value=0.1uF
C32 "GCM32EC71A476KE02K" 1210_270 81.676,57.773 r180 top value=47uF
C33 "GCM32EC71A476KE02K" 1210_270 81.677,4.28 r180 top value=47uF
C34 "GCM32EC71A476KE02K" 1210_270 81.677,17.75 r180 top value=47uF
C35 "GCM1885C2A100JA16D" 0603L 29.939,33.069 r180 top value=10pF
C36 "GCM1885C2A100JA16D" 0603L 30.193,75.737 r0 top value=10pF
C37 "GCM188R71E104KA57D" 0603L 36.125,72.113 r0 top value=0.1uF
C38 "GCM188R71E104KA57D" 0603L 36.57,30.325 r0 top value=0.1uF
C39 "GRT188C71C475KE13D" FP-GRT188C71C475KE13D_0603-MFG 36.125,69.264 r180 top value=4.7µF
C40 "GRT188C71C475KE13D" FP-GRT188C71C475KE13D_0603-MFG 36.472,27.568 r180 top value=4.7µF
C41 "GCM188R71C105KA64J" 0603L 22.866,68.412 r180 top value=1uF
C42 "HMK107B7104KAHT" 0603L 33.109,62.616 r270 top value=0.1uF
C43 "HMK107B7104KAHT" 0603L 33.084,20.668 r270 top value=0.1uF
C44 "GCM188R71C105KA64J" 0603L 22.845,26.623 r180 top value=1uF
C45 "GCM188R71E104KA57D" 0603L 36.174,66.023 r0 top value=0.1uF
C46 "GCM188R71E104KA57D" 0603L 36.543,24.049 r0 top value=0.1uF
C47 "HMK107B7104KAHT" 0603 112.273,41.803 r270 top value=0.1uF
C48 "CGA3E2X7R2A222K080AA" 0603L 21.532,74.218 r180 top value=2200pF
C49 "CGA3E2X7R2A103K080AA" 0603 54.338,75.892 r180 top value=0.01uF
C50 "CGA3E2X7R2A103K080AA" 0603 54.338,79.238 r180 top value=0.01uF
C51 "CGA3E2X7R2A103K080AA" 0603 54.338,80.91 r180 top value=0.01uF
C52 "CGA3E2X7R2A103K080AA" 0603 54.338,77.565 r180 top value=0.01uF
C53 "CGA6P3X7S1H106K250AE" 1210_280 45.491,58.374 r180 top value=10uF
C54 "CGA6P3X7S1H106K250AE" 1210_280 45.491,64.934 r180 top value=10uF
C55 "CGA6P3X7S1H106K250AE" 1210_280 60.104,66.621 r0 top value=10uF
C56 "CGA6P3X7S1H106K250AE" 1210_280 60.194,70.302 r0 top value=10uF
C57 "CGA3E2X7R2A103K080AA" 0603 54.338,82.583 r180 top value=0.01uF
C58 "CGA6P3X7S1H106K250AE" 1210_280 45.491,61.657 r180 top value=10uF
C59 "CGA6P3X7S1H106K250AE" 1210_280 60.194,45.746 r0 top value=10uF
C60 "CGA3E2X7R2A103K080AA" 0603 54.338,41.43 r180 top value=0.01uF
C61 "CGA6P3X7S1H106K250AE" 1210_280 45.491,38.002 r180 top value=10uF
C62 "CGA6P3X7S1H106K250AE" 1210_280 45.491,34.696 r180 top value=10uF
C63 "CGA6P3X7S1H106K250AE" 1210_280 45.491,31.383 r180 top value=10uF
C64 "CGA6P3X7S1H106K250AE" 1210_280 45.491,68.226 r180 top value=10uF
C65 "CGA3E2X7R2A103K080AA" 0603 54.338,37.884 r180 top value=0.01uF
C66 "CGA3E2X7R2A103K080AA" 0603 54.338,39.657 r180 top value=0.01uF
C67 "GCM32EC71A476KE02K" 1210_270 81.677,77.27 r180 top value=47uF
C68 "GCM32EC71A476KE02K" 1210_270 81.677,80.917 r180 top value=47uF
C69 "GCM32EC71A476KE02K" 1210_270 81.676,64.671 r180 top value=47uF
C70 "GCM188R71E104KA57D" 0603 102.606,58.474 r270 top value=0.1uF
C71 "GCM188R71E104KA57D" 0603 102.572,27.895 r90 top value=0.1uF
C72 "GCM32EC71A476KE02K" 1210_270 81.677,21.265 r180 top value=47uF
C73 "GCM32EC71A476KE02K" 1210_270 81.677,24.78 r180 top value=47uF
C74 "GCM32EC71A476KE02K" 1210_270 81.677,37.924 r180 top value=47uF
C75 "GCM1885C2A100JA16D" 0603L 28.833,63.348 r0 top value=10pF
C76 "GCM1885C2A100JA16D" 0603L 29.064,21.301 r180 top value=10pF
C77 "CGA3E2X7R2A103K080AA" 0603 54.338,20.341 r180 top value=0.01uF
C78 "CGA3E2X7R2A103K080AA" 0603 54.338,18.488 r180 top value=0.01uF
C79 "CGA3E2X7R2A103K080AA" 0603 54.338,43.203 r180 top value=0.01uF
C80 "CGA3E2X7R2A103K080AA" 0603 54.338,36.111 r180 top value=0.01uF
C81 "HMK107B7104KAHT" 0603 112.22,47.749 r270 top value=0.1uF
C82 "CGA3E2NP01H330J080AA" 0603L 21.532,72.93 r180 top value=33pF
C83 "GCM21BR72A104KA37L" 0805_HV 18.613,52.184 r90 top value=0.1uF
C84 "GCM32EC71A476KE02K" 1210_270 99.572,46.429 r270 top value=47uF
C85 "GCM32EC71A476KE02K" 1210_270 103.447,46.429 r270 top value=47uF
C86 "GCM32EC71A476KE02K" 1210_270 99.572,52.965 r90 top value=47uF
C87 "GCM32EC71A476KE02K" 1210_270 96.001,52.965 r90 top value=47uF
C88 "GCM32EC71A476KE02K" 1210_270 92.395,52.965 r90 top value=47uF
C89 "GCM32EC71A476KE02K" 1210_270 92.395,58.732 r270 top value=47uF
C90 "GCM32EC71A476KE02K" 1210_270 96.001,58.732 r270 top value=47uF
C91 "GCM32EC71A476KE02K" 1210_270 99.572,58.732 r270 top value=47uF
C92 "GCM32EC71A476KE02K" 1210_270 96.001,46.429 r270 top value=47uF
C93 "GCM32EC71A476KE02K" 1210_270 92.395,46.429 r270 top value=47uF
C94 "GCM32EC71A476KE02K" 1210_270 92.395,39.858 r90 top value=47uF
C95 "GCM32EC71A476KE02K" 1210_270 96.001,39.858 r90 top value=47uF
C96 "GCM32EC71A476KE02K" 1210_270 99.572,27.942 r90 top value=47uF
C97 "GCM32EC71A476KE02K" 1210_270 99.572,33.663 r270 top value=47uF
C98 "GCM32EC71A476KE02K" 1210_270 96.001,33.663 r270 top value=47uF
C99 "GCM32EC71A476KE02K" 1210_270 92.395,33.663 r270 top value=47uF
C100 "GCM32EC71A476KE02K" 1210_270 96.001,27.942 r90 top value=47uF
C101 "GCM32EC71A476KE02K" 1210_270 92.395,27.942 r90 top value=47uF
C102 "GCM32EC71A476KE02K" 1210_270 103.447,39.858 r90 top value=47uF
C103 "GCM32EC71A476KE02K" 1210_270 99.572,39.858 r90 top value=47uF
C104 "EEE-FK1A151P" SM_RADIAL_D 103.25,28.638 r90 bottom value=150uF
C105 "EEE-FK1A151P" SM_RADIAL_D 103.25,58.984 r270 bottom value=150uF
C106 "EEE-FK1A151P" SM_RADIAL_D 103.25,47.801 r270 bottom value=150uF
C107 "EEE-FK1A151P" SM_RADIAL_D 103.25,38.96 r90 bottom value=150uF
C108 "CGA3E2X7R1E104K080AA" 0603L 22.862,75.775 r0 top value=0.1uF
C109 "CGA3E2X7R1E104K080AA" 0603L 26.354,33.746 r270 top value=0.1uF
C110 "CGA3E2X7R1E104K080AA" 0603L 26.098,62.687 r90 top value=0.1uF
C111 "CGA3E2X7R1E104K080AA" 0603L 22.845,25.206 r0 top value=0.1uF
FID1 "Fiducial" Fiducial10-20 5.08,74.766 r0 top
FID2 "Fiducial" Fiducial10-20 5,14 r0 top
FID3 "Fiducial" Fiducial10-20 109.728,7.62 r0 top
H1 "NY PMS 440 0025 PH" "NY PMS 440 0025 PH" 5.08,82.55 r0 top locked
H2 "NY PMS 440 0025 PH" "NY PMS 440 0025 PH" 120.65,82.55 r0 top locked
H3 "NY PMS 440 0025 PH" "NY PMS 440 0025 PH" 5.08,5.08 r0 top locked
H4 "NY PMS 440 0025 PH" "NY PMS 440 0025 PH" 120.65,5.08 r0 top locked
H5 "1902C" Keystone_1902C 5.08,82.55 r180 bottom locked
H6 "1902C" Keystone_1902C 120.65,82.55 r180 bottom locked
H7 "1902C" Keystone_1902C 5.08,5.08 r180 bottom locked
H8 "1902C" Keystone_1902C 120.65,5.08 r180 bottom locked
J1 "5-146261-1" CONN_5-146261-1 124.411,41.5 r90 top
J2 "MMCX-J-P-H-ST-TH1" Samtec_MMCX-J-P-H-ST-TH1 108.95,38.321 r90 top
J3 "MMCX-J-P-H-ST-TH1" Samtec_MMCX-J-P-H-ST-TH1 108.886,52.316 r90 top
J4 "TS-108-G-AA" Samtec_TS-108-x-AA 25.832,85.05 r0 top
J5 "TS-108-G-AA" Samtec_TS-108-x-AA 25.832,3.25 r0 top
L1 "SRP1245A-R22M" SRP1245A 27.334,47.684 r0 top value=220nH
L2 "VCHA105D-1R5MS6" FP-VCHA105D-1R5MS6_SMT2_10MM85_10MM0-MFG 71.339,71.568 r0 top value=1.5uH
L3 "VCHA105D-1R5MS6" FP-VCHA105D-1R5MS6_SMT2_10MM85_10MM0-MFG 71.339,30.483 r180 top value=1.5uH
L4 "VCHA105D-1R5MS6" FP-VCHA105D-1R5MS6_SMT2_10MM85_10MM0-MFG 71.339,51.195 r0 top value=1.5uH
L5 "VCHA105D-1R5MS6" FP-VCHA105D-1R5MS6_SMT2_10MM85_10MM0-MFG 71.339,9.816 r180 top value=1.5uH
LBL1 "THT-14-423-10" Label_650x200 101.678,76.23 r0 top
Logo1 "CE Mark" CE_Mark_5mm 97.569,14.102 r0 top
Logo2 "Texas Instruments" TI_Stacked_Overlay_Small 103.5,-15 r0 top
Logo3 "FCC disclaimer" FCC_disclaimer 84.75,114.25 r0 top
Logo4 "WEEE logo" WEEE_Minimum 107.019,15.072 r0 top
Q1 "IPC50N04S5L5R5ATMA1" PG-TDSON-8-33 60.917,80.553 r180 top value=40V
Q2 "IPC50N04S5L5R5ATMA1" PG-TDSON-8-33 60.917,39.467 r180 top value=40V
Q3 "IPC50N04S5L5R5ATMA1" PG-TDSON-8-33 69.513,39.467 r180 top value=40V
Q4 "IPC50N04S5L5R5ATMA1" PG-TDSON-8-33 69.513,80.553 r180 top value=40V
Q5 "IPC50N04S5L5R5ATMA1" PG-TDSON-8-33 60.917,60.271 r180 top value=40V
Q6 "IPC50N04S5L5R5ATMA1" PG-TDSON-8-33 60.917,18.769 r180 top value=40V
Q7 "IPC50N04S5L5R5ATMA1" PG-TDSON-8-33 69.513,60.271 r180 top value=40V
Q8 "IPC50N04S5L5R5ATMA1" PG-TDSON-8-33 69.513,18.769 r180 top value=40V
Q9 "CSD16556Q5B" DNK0008A 116.511,46.014 r90 top value=25V
R1 "RC0603FR-100RL" FP-RC0603FR-100RL_0603-MFG 28.591,78.375 r0 top value=0
R2 "CRCW060375K0FKEA" 0603L 28.761,79.899 r0 top value=75.0k
R3 "CRCW060316K2FKEA" 0603L 25.576,79.899 r0 top value=16.2k
R4 "KRL6432E-M-R003-F-T1" FP-KRL6432E-M-R003-F-T1_2512-MFG 81.676,71.558 r0 top value=3m
R5 "KRL6432E-M-R003-F-T1" FP-KRL6432E-M-R003-F-T1_2512-MFG 81.5,30.403 r180 top value=3m
R6 "CRCW0603249RFKEA" 0603L 30.872,77.675 r90 top value=249
R7 "CRCW0603249RFKEA" 0603L 30.661,35 r90 top value=249
R8 "CRCW060310K0FKEA" 0603L 22.856,77.155 r180 top value=10.0k
R9 "CRCW060310K0FKEA" 0603L 25.077,33.746 r90 top value=10.0k
R10 "RC0603FR-100RL" FP-RC0603FR-100RL_0603-MFG 36.222,70.831 r0 top value=0
R11 "RC0603FR-100RL" FP-RC0603FR-100RL_0603-MFG 36.57,29.064 r0 top value=0
R12 "CRCW06031R54FKEA" 0603 121.25,43.25 r180 top value=1.54
R13 "CRCW060375K0FKEA" 0603L 27.724,76.412 r90 top value=75.0k
R14 "CRCW060318K0JNEA" 0603L 23.56,73.605 r270 top value=18k
R15 "RC0603FR-100RL" FP-RC0603FR-100RL_0603-MFG 36.199,67.372 r0 top value=0
R16 "RC0603FR-100RL" FP-RC0603FR-100RL_0603-MFG 36.57,25.347 r0 top value=0
R17 "CRCW060341K2FKEA" 0603L 25.203,76.412 r270 top value=41.2k
R18 "CRCW060320K0FKEA" 0603L 22.866,71.597 r0 top value=20.0k
R19 "CRCW060357K6FKEA" 0603L 22.866,70.214 r0 top value=57.6k
R20 "CRCW060390K9FKEA" 0603L 27.617,33.746 r270 top value=90.9k
R21 "CRCW060357K6FKEA" 0603L 22.917,28.348 r0 top value=57.6k
R22 "CRCW0603100KFKEA" 0603L 20.105,78 r0 top value=100k
R23 "CRCW060310K0FKEA" 0603L 24.795,62.687 r270 top value=10.0k
R24 "CRCW060310K0FKEA" 0603L 22.845,23.892 r180 top value=10.0k
R25 "CRCW0603100KFKEA" 0603L 34.227,78.375 r0 top value=100k
R26 "CRCW0603100KFKEA" 0603L 34.298,76.341 r0 top value=100k
R27 "CRCW0603100KFKEA" 0603L 31.895,62.616 r270 top value=100k
R28 "CRCW0603100KFKEA" 0603L 34.75,33.675 r90 top value=100k
R29 "CRCW0603100KFKEA" 0603L 31.859,20.668 r270 top value=100k
R30 "CRCW06031K00JNEA" 0603L 22.231,80.129 r90 top value=1.0k
R31 "CRCW06031K00JNEA" 0603L 22.937,64.607 r0 top value=1.0k
R32 "CRCW06031K00JNEA" 0603L 32.96,33.744 r270 top value=1.0k
R33 "CRCW06031K00JNEA" 0603L 35.004,21.378 r180 top value=1.0k
R34 "CRCW060320K0FKEA" 0603L 20.843,80.129 r270 top value=20.0k
R35 "RC0603FR-100RL" FP-RC0603FR-100RL_0603-MFG 22.966,66.591 r0 top value=0
R40 "KRL6432E-M-R003-F-T1" FP-KRL6432E-M-R003-F-T1_2512-MFG 81.588,51.195 r0 top value=3m
R41 "KRL6432E-M-R003-F-T1" FP-KRL6432E-M-R003-F-T1_2512-MFG 81.5,9.816 r180 top value=3m
R42 "CRCW0603249RFKEA" 0603L 29.533,61.275 r270 top value=249
R43 "CRCW0603249RFKEA" 0603L 29.764,19.286 r270 top value=249
R46 "TNPW060310K0BEEA" TNPW0603 120.386,41.328 r90 top value=10.0k
R47 "CRCW060349K9FKEA" 0603 109.746,42.608 r180 top value=49.9k
R48 "CRCW060349K9FKEA" 0603 109.65,48.549 r0 top value=49.9k
R49 "CRA2512-FZ-R010ELF" 2512 115.876,38 r90 top value=0.01
R50 "CRCW060316K2FKEA" 0603L 26.495,76.412 r270 top value=16.2k
T1 "CB35-36-CY" CB35-36-CY 8.5,61.25 r0 top
T2 "CB35-36-CY" CB35-36-CY 8.5,27 r0 top
T3 "CB35-36-CY" CB35-36-CY 117.15,61.25 r180 top
T4 "CB35-36-CY" CB35-36-CY 117.15,27 r180 top
U1 "LM5137FDQRHARQ1" RHA0036D-MFG 29.872,69.073 r90 top
U2 "LM5137FDQRHARQ1" RHA0036D-MFG 29.867,27.198 r90 top
ZZ1 "This Assembly Note is for PCB labels only" AssemblyNoteLabel 141.423,10.286 r90 top
ZZ2 "These assemblies are ESD sensitive, ESD precautions shall be observed." AssemblyNote 136.923,73.286 r90 top
ZZ3 "These assemblies must be clean and free from flux and all contaminants. Use of no clean flux is not acceptable." AssemblyNote 132.423,34.036 r90 top
ZZ4 "These assemblies must comply with workmanship standards IPC-A-610 Class 2, unless otherwise specified." AssemblyNote 127.923,42.286 r90 top

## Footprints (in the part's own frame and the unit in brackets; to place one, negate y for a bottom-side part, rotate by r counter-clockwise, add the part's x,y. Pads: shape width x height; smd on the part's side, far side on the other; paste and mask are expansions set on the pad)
0603 [mm] "0603 from SM-752 data"
  rect 1x0.95 smd: 1(-0.8,0) 2(0.8,0)
  silkscreen extent -1.52,-0.69 1.52,0.69, body extent -0.87,-0.47 0.87,0.47, height 1
0603L [mm] "0603 from SM-752 data"
  rect 0.8x0.85 smd: 1(-0.7,0) 2(0.7,0)
  silkscreen extent -0.07,-0.33 0.07,0.33, body extent -0.87,-0.47 0.87,0.47, height 1
0805_HV [mil] "0805 with 30mil clearance between pads"
  rect 50x63 smd: 1(-40,0) 2(40,0)
  silkscreen extent -74,-40 74,40, body extent -43,-29 43,29, height 57
0805L [mm] "0805 from SM-752 data"
  rect 1.1x1.4 smd: 1(-0.75,0) 2(0.75,0)
  body extent -1.1,-0.72 1.1,0.72, height 1.45
1210_270 [mm] "1210"
  rect 1.3x2.7 smd: 1(-1.45,0) 2(1.45,0)
  silkscreen extent -2.32,-1.57 2.32,1.57, body extent -1.7,-1.35 1.7,1.35, height 2.7
1210_280 [mm] "SMD, 2-Leads, Body 3.6x2.8mm, Height 2.8mm"
  rect 1.1x2.2 smd: 1(-1.65,0) 2(1.65,0)
  silkscreen extent -0.84,-1.4 0.84,1.4, body extent -1.8,-1.4 1.8,1.4, height 2.8
2512 [mm] "Chip Resistor, Body 6.3x3.2mm, IPC Medium Density"
  rect 1.3x3.4 smd: 1(-2.95,0) 2(2.95,0)
  silkscreen extent -1.9,-1.6 1.9,1.6, body extent -3.22,-1.67 3.22,1.67, height 0.71
AssemblyNote [mm] "Assembly Note"
AssemblyNoteLabel [mm] "Assembly Note for PCB Labels"
CB35-36-CY [mil] "Terminal 50A Lug"
  rect 550x380 hole 188 copper offset -45,0 paste-190: 1(0,0)
  body extent -960,-189 230,191, height 614
CE_Mark_5mm [mm] "Minimum text height for CE Mark"
  silkscreen extent -3.5,-2.5 3.5,2.5
CONN_5-146261-1 [mm] "Sullins"
  rect 1.5x1.5 hole 1.02: 1(-1.27,0)
  round 1.5 hole 1.02: 2(1.27,0)
  silkscreen extent -3.68,-1.27 2.54,1.27, body extent -2.51,-1.27 2.51,1.27, height 10.87
DNK0008A [mm] "SON, 8-Leads, Body 5x6mm"
  rrect39% 0.86x0.51 smd paste-0.05 mask-0.05: 1(-2.82,1.905) 2(-2.82,0.635) 3(-2.82,-0.635) 4(-2.82,-1.905) 5(2.82,-1.905) 6(2.82,-0.635) 7(2.82,0.635) 8(2.82,1.905)
  rrect40% 0.25x0.555 on Top Solder: 9(-0.83,2.372) 9(-0.83,-2.372)
  rrect40% 0.25x0.555 on Top Paste: 9(-0.83,2.372) 9(-0.83,-2.372)
  rrect11% 0.95x1.13 on Top Paste: 9(-0.535,1.33) 9(-0.535,0) 9(-0.535,-1.33) 9(0.615,1.33) 9(0.615,0) 9(0.615,-1.33) 9(1.765,-1.33) 9(1.765,0) 9(1.765,1.33)
  rrect3% 3.58x4 on Top Solder: 9(0.75,0)
  rrect5% 4.34x5.4 smd paste-3 mask-3: 9(1.08,0)
  body extent -3.05,-2.55 3.05,2.55, height 1.06
FCC_disclaimer [mm]
Fiducial10-20 [mm]
  round 1 smd mask+0.5: 1(0,0)
  Top Layer keep-out circle w1.178: c0,0 r0.5
FP-GRT188C71C475KE13D_0603-MFG [mm]
  rrect13% 0.75x0.9 smd paste+0 mask+0: 1(-0.775,0) 2(0.775,0)
  silkscreen extent 0,-0.5 0,0.5, body extent -1.25,-0.6 1.25,0.6, height 0.25
FP-KRL6432E-M-R003-F-T1_2512-MFG [mm]
  rrect10% 1x6.6 smd paste+0 mask+0: 1(-1.6,0) 2(1.6,0)
  silkscreen extent -0.72,-3.25 0.72,3.25, body extent -1.55,-3.15 1.55,3.15, height 0.7
FP-RC0603FR-100RL_0603-MFG [mm]
  rrect13% 0.9x0.8 smd paste+0 mask+0: 1(-0.85,0) 2(0.85,0)
  silkscreen extent 0,-0.45 0,0.45, body extent -1.4,-0.55 1.4,0.55, height 0.25
FP-VCHA105D-1R5MS6_SMT2_10MM85_10MM0-MFG [mm]
  rrect3% 3.99x5 smd paste+0 mask+0: 1(-4.445,0) 2(4.445,0)
  silkscreen extent -7.12,-5.15 5.6,5.15, body extent -6.54,-5.25 6.54,5.25, height 0.25
Keystone_1902C [mil] "Hex Standoff, 4-40 threaded, nylon"
  round 1 on Mech4: 0(0,0)
  body extent -145,-126 146,126, height 501
Label_650x200 [mil] "Thermal Transfer Label"
  round 1 on Mech13: 0(0,0)
  silkscreen extent -325,-100 325,100, body extent -325,-100 325,100, height 1
"NY PMS 440 0025 PH" [mm] "4-40 nylon screw and mounting hole"
  round 8 hole 3.2: 1(0,0)
  body extent -3.3,-3.3 3.3,3.3, height 2.69
PG-TDSON-8-33 [mm] "Infineon recommended land pattern"
  rrect29% 1.65x0.7 smd paste-1 mask-0.05: 1(-2.995,1.905) 2(-2.995,0.635) 3(-2.995,-0.635) 4(-2.995,-1.905) 5(2.995,-1.905) 6(2.995,-0.635) 7(2.995,0.635) 8(2.995,1.905)
  Top Layer region: -3.82,-0.565 -3.82,1.835 -3.816,1.854 -3.805,1.87 -3.789,1.881 -3.77,1.885 -3.77,1.885 -2.22,1.885 -2.201,1.881 -2.185,1.87 -2.174,1.854 -2.17,1.835 -2.17,1.835 -2.17,-0.565 -2.174,-0.584 -2.185,-0.6 -2.201,-0.611 -2.22,-0.615 -2.22,-0.615 -3.77,-0.615 -3.789,-0.611 -3.805,-0.6 -3.816,-0.584 -3.82,-0.565
  Top Layer region: -1.18,-2.155 -1.18,2.155 -1.172,2.193 -1.151,2.226 -1.118,2.247 -1.08,2.255 -1.08,2.255 3.72,2.255 3.758,2.247 3.791,2.226 3.812,2.193 3.82,2.155 3.82,2.155 3.82,-2.155 3.812,-2.193 3.791,-2.226 3.758,-2.247 3.72,-2.255 3.72,-2.255 -1.08,-2.255 -1.118,-2.247 -1.151,-2.226 -1.172,-2.193 -1.18,-2.155
  body extent -3.22,-2.71 3.22,2.7, height 1.01
RHA0036D-MFG [mm]
  rrect40% 0.6x0.25 smd paste+0 mask+0: 1(-2.9,2.25) 2(-2.9,1.75) 3(-2.9,0.75) 4(-2.9,0.25) 5(-2.9,-0.25) 6(-2.9,-0.75) 7(-2.9,-1.25) 8(-2.9,-1.75) 9(-2.9,-2.25) 18(2.9,-2.25) 19(2.9,-1.75) 20(2.9,-1.25) 21(2.9,-0.75) 22(2.9,-0.25) 23(2.9,0.25) 24(2.9,1.25) 25(2.9,1.75) 26(2.9,2.25)
  rrect40% 0.25x0.6 smd paste+0 mask+0: 10(-2.25,-2.9) 11(-1.75,-2.9) 12(-0.75,-2.9) 13(-0.25,-2.9) 14(0.25,-2.9) 15(0.75,-2.9) 16(1.75,-2.9) 17(2.25,-2.9) 27(2.25,2.9) 28(1.75,2.9) 29(1.25,2.9) 30(0.75,2.9) 31(0.25,2.9) 32(-0.25,2.9) 33(-0.75,2.9) 34(-1.25,2.9) 35(-1.75,2.9) 36(-2.25,2.9)
  rrect3% 3.3x3.3 smd paste-1000 mask+0: 37(0,0)
  silkscreen extent -3.87,-3.05 3.05,3.05, body extent -3.3,-3.3 3.3,3.3, height 0.25
Samtec_MMCX-J-P-H-ST-TH1 [mm] "Connector, MMCX, TH"
  round 1.2 hole 0.84: 1(0,0) 2(-1.27,1.27) 3(1.27,1.27) 4(1.27,-1.27) 5(-1.27,-1.27)
  silkscreen extent -1.75,-1.75 1.75,1.75, body extent -1.75,-1.75 1.75,1.75, height 4.35
Samtec_TS-108-x-AA [mil] "Header, 2.54mm, 8x1, TH"
  rrect50% 37.5x37.5 hole 25: 1(-350,0)
  round 37.5 hole 25: 2(-250,0) 3(-150,0) 4(-50,0) 5(50,0) 6(150,0) 7(250,0) 8(350,0)
  body extent -404,-50 404,50, height 326
SM_RADIAL_D [mm] "6.3 x 5.8mm:  Panasonic D"
  rect 3.2x1.6 smd: 1(-2.5,0) 2(2.5,0)
  silkscreen extent -3.4,-3.4 3.4,3.4, body extent -3.4,-3.4 3.4,3.4, height 6.1
SM_RADIAL_H13 [mm] "12.5 x 13.5mm:  Panasonic H13"
  rect 5.7x2 smd: 1(-4.85,0) 2(4.85,0)
  silkscreen extent -6.85,-6.85 6.85,6.85, body extent -6.85,-6.85 6.85,6.85, height 14
SRP1245A [mm] "SMD, 2-Leads, Body 13.5x12.5mm"
  rect 3.1x5 smd: 1(-5.55,0) 2(5.55,0)
  silkscreen extent -6.25,-6.25 6.25,6.25, body extent -6.45,-6.25 6.45,6.25, height 5
TI_Stacked_Overlay_Small [mm]
  silkscreen extent -10.63,-2.49 10.63,2.49
TNPW0603 [mm] "Vishay"
  rect 0.5x0.9 smd: 1(-0.75,0) 2(0.75,0)
  silkscreen extent -0.2,-0.6 0.2,0.6, body extent -0.85,-0.47 0.85,0.47, height 0.55
WEEE_Minimum [mm] "WEEElie bin"
  silkscreen extent -2.42,-4.38 2.52,2.65

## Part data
C1 C2 C3 C4 C9 C12 C17 C18 C49 C50 C51 C52 C57 C60 C65 C66 C77 C78 C79 C80: library part CMP-0007082-1, "CAP, CERM, 0.01 uF, 100 V, +/- 10%, X7R, AEC-Q200 Grade 1, 0603", Cap_Case=0603, Manufacturer=TDK, Supplier Part Number 1=445-5812-1-ND, TempCo=X7R, Tolerance_%=10%, Value1="0.235428 ohm", Value2=100V, ValueDisplayed=0.01uF
C5 C6 C7 C8 C10 C11 C13 C14 C15 C16 C20 C21 C53 C54 C55 C56 C58 C59 C61 C62 C63 C64: library part CMP-0085350-1, "CAP, CERM, 10 µF, 50 V,+/- 10%, X7S, AEC-Q200 Grade 1, 1210", Cap_Case=1210, Manufacturer=TDK, TempCo=X7S, Tolerance_%=10%, Value2=50V, ValueDisplayed=10µF
C19 C83: library part CMP-0860440-1, "CAP, CERM, 0.1 µF, 100 V,+/- 10%, X7R, AEC-Q200 Grade 1, 0805", Cap_Case=0805, Manufacturer=MuRata, TempCo=X7R, Tolerance_%=10%, Value2=100V, ValueDisplayed=0.1µF
C22 C23 C24 C25: library part CMP-0860897-1, "CAP, CERM, 2.2 µF, 50 V,+/- 10%, X7R, AEC-Q200 Grade 1, 0805", Cap_Case=0805, Manufacturer=TDK, TempCo=X7R, Tolerance_%=10%, Value2=50V, ValueDisplayed=2.2µF
C26: library part CMP-0011211-2, "CAP, AL, 330 uF, 50 V, +/- 20%, 0.12 ohm, AEC-Q200 Grade 2, SMD", Cap_Case=H13, Manufacturer=Panasonic, Supplier Part Number 1=PCE3475CT-ND, Tolerance_%=20%, Value1="0.12 ohm", Value2=50V, ValueDisplayed=330uF
C27 C28 C29 C32 C33 C34 C67 C68 C69 C72 C73 C74 C84 C85 C86 C87 C88 C89 C90 C91 C92 C93 C94 C95 C96 C97 C98 C99 C100 C101 C102 C103: library part CMP-0079933-1, "CAP, CERM, 47 µF, 10 V,+/- 10%, X7S, AEC-Q200 Grade 1, 1210", Cap_Case=1210, Manufacturer=MuRata, TempCo=X7S, Tolerance_%=10%, Value2=10V, ValueDisplayed=47µF
C30 C31 C37 C38 C45 C46 C70 C71: library part CMP-0084679-1, "CAP, CERM, 0.1 µF, 25 V,+/- 10%, X7R, AEC-Q200 Grade 1, 0603", Cap_Case=0603, Manufacturer=MuRata, TempCo=X7R, Tolerance_%=10%, Value2=25V, ValueDisplayed=0.1µF
C35 C36 C75 C76: library part CMP-0084283-1, "CAP, CERM, 10 pF, 100 V,+/- 5%, C0G/NP0, AEC-Q200 Grade 1, 0603", Cap_Case=0603, Manufacturer=MuRata, TempCo=C0G/NP0, Tolerance_%=5%, Value2=100V, ValueDisplayed=10pF
C39 C40: library part CMP-0098105-1, "AEC-Q200 Compliant Chip Multilayer Ceramic Capacitor for Infotainment 4.7uF ±10% 16V X7S SMD 0603", Digikey Part Number=490-GRT188C71C475KE13DCT-ND, Manufacturer=Murata, Mouser Part Number=81-GRT188C71C475KE13, Operating Temperature Range="-55°C to +125°C", TempCo=22%, Temperature Characteristic=X7S, Tolerance_%=10%, ValueDisplayed=4.7uF
C41 C44: library part CMP-0079154-1, "CAP, CERM, 1 µF, 16 V,+/- 10%, X7R, AEC-Q200 Grade 1, 0603", Cap_Case=0603, Manufacturer=MuRata, Supplier Part Number 1=490-12657-1-ND, TempCo=X7R, Tolerance_%=10%, Value2=16V, ValueDisplayed=1µF
C42 C43 C47 C81: library part CMP-0081011-1, "CAP, CERM, 0.1 µF, 100 V,+/- 10%, X7R, AEC-Q200 Grade 1, 0603", Cap_Case=0603, Manufacturer="Taiyo Yuden", Supplier Part Number 1=587-6009-1-ND, TempCo=X7R, Tolerance_%=10%, Value2=100V, ValueDisplayed=0.1µF
C48: library part CMP-0007085-1, "CAP, CERM, 2200 pF, 100 V, +/- 10%, X7R, AEC-Q200 Grade 1, 0603", Cap_Case=0603, Manufacturer=TDK, Supplier Part Number 1=445-5808-1-ND, TempCo=X7R, Tolerance_%=10%, Value1="0.923948 ohm", Value2=100V, ValueDisplayed=2200pF
C82: library part CMP-0007076-2, "CAP, CERM, 33 pF, 50 V, +/- 5%, C0G/NP0, AEC-Q200 Grade 0, 0603", Cap_Case=0603, Manufacturer=TDK, Supplier Part Number 1=445-12409-1-ND, TempCo=C0G/NP0, Tolerance_%=5%, Value1=Unknown, Value2=50V, ValueDisplayed=33pF
C104 C105 C106 C107: library part CMP-0010687-1, "CAP, AL, 150 uF, 10 V, +/- 20%, 0.36 ohm, AEC-Q200 Grade 2, SMD", Cap_Case=D, Manufacturer=Panasonic, Supplier Part Number 1=PCE3773CT-ND, Tolerance_%=20%, Value1="0.36 ohm", Value2=10V, ValueDisplayed=150uF
C108 C109 C110 C111: library part CMP-0007077-5, "CAP, CERM, 0.1 uF, 25 V, +/- 10%, X7R, AEC-Q200 Grade 1, 0603", Cap_Case=0603, Manufacturer=TDK, Supplier Part Number 1=445-5667-1-ND, TempCo=X7R, Tolerance_%=10%, Value1=Unknown, Value2=25V, ValueDisplayed=0.1uF
FID1 FID2 FID3: library part CMP-0077181-1, "Fiducial mark.  There is nothing to buy or mount.", Manufacturer=N/A
H1 H2 H3 H4: library part CMP-0003617-1, "Machine Screw, Round, #4-40 x 1/4, Nylon, Philips panhead", Manufacturer="B&F Fastener Supply", Supplier Part Number 1=H542-ND
H5 H6 H7 H8: library part CMP-0003610-1, "Standoff, Hex, 0.5\"L #4-40 Nylon", Manufacturer=Keystone, Supplier Part Number 1=36-1902C-ND
J1: library part CMP-0054947-1, "Header, 100mil, 2x1, Gold, TH", Manufacturer="TE Connectivity"
J2 J3: library part CMP-0075554-1, "Connector, MMCX 50 ohm, TH", Manufacturer=Samtec, Supplier Part Number 1=88K0549
J4 J5: library part CMP-0084415-1, "Header, 2.54mm, 8x1, Gold, TH", Color=Black, Manufacturer=Samtec
L1: library part CMP-0056879-1, "Inductor, Wirewound, 220 nH, 52 A, 0.0005 ohm, AEC-Q200 Grade 0, SMD", Manufacturer=Bourns, Supplier Part Number 1=41Y0261, Value1="0.0005 ohm", Value2=52A, ValueDisplayed=220nH
L2 L3 L4 L5: library part CMP-0095579-1, "Power Choke Coil VCHA105D MS6 type 1.5uH 20% 4.2mOhm 24.8A", Manufacturer=Cyntec, Operating Temperature Range="-55°C to +165°C", Test Frequency=100kHz, Tolerance_%=20%
LBL1: library part CMP-0003625-1, "Thermal Transfer Printable Labels, 0.650\" W x 0.200\" H - 10,000 per roll", Manufacturer=Brady, Supplier Part Number 1=97C5133
Logo1: library part CMP-0074844-1
Logo2: library part CMP-0074838-1, "Texas Instrument Corporate Signature"
Logo3: library part CMP-0074847-1, "FCC_disclaimer"
Logo4: library part CMP-0074769-1
Q1 Q2 Q3 Q4 Q5 Q6 Q7 Q8: library part CMP-0080659-3, "MOSFET, N-CH, 40 V, 50 A, AEC-Q101, SON-8", Alternate Manufacturer=None, Manufacturer="Infineon Technologies", Supplier Part Number 1=IPC50N04S5L5R5ATMA1CT-ND, Value1="0.0079 ohm", Value2="17 nC"
Q9: library part CMP-0000273-2, "MOSFET, N-CH, 25 V, 40 A, DNK0008A (VSON-CLIP-8)", Alternate Manufacturer=None, Manufacturer="Texas Instruments", Supplier Part Number 1=296-35627-1-ND, Value1=0.001, Value2="36 nC"
R1 R10 R11 R15 R16 R35: library part CMP-0123755-1, "0 Ohms Jumper Chip Resistor 0603 (1608 Metric) Moisture Resistant Thick Film", Digikey Part Number=13-RC0603FR-100RLCT-ND, Manufacturer=Yageo, Mouser Part Number=603-RC0603FR-100RL, Operating Temperature Range="-55°C to +155°C", Tolerance_%=1%
R2 R13: library part CMP-0022589-4, "RES, 75.0 k, 1%, 0.1 W, AEC-Q200 Grade 0, 0603", Manufacturer=Vishay-Dale, Power_W=100mW, Supplier Part Number 1=541-75.0KHCT-ND, TempCo="100 ppm/C", Tolerance_%=1%, Value2=0.1W, Value_Code=75k0, ValueDisplayed=75.0k
R3 R50: library part CMP-0022079-4, "RES, 16.2 k, 1%, 0.1 W, AEC-Q200 Grade 0, 0603", Manufacturer=Vishay-Dale, Power_W=100mW, Supplier Part Number 1=541-16.2KHCT-ND, TempCo="100 ppm/C", Tolerance_%=1%, Value2=0.1W, Value_Code=16k2, ValueDisplayed=16.2k
R4 R5 R40 R41: library part CMP-0122627-1, "3 mOhms ±1% 3W Chip Resistor Wide 2512 (6432 Metric), 1225 Automotive AEC-Q200, Current Sense Metal Foil", Digikey Part Number=408-1613-1-ND, Manufacturer=Susumu, Mouser Part Number=754-KRL6432EMR003FT1, Operating Temperature Range="-55°C to +155°C", Power_W=3W, TempCo=50ppm/°C, Tolerance_%=1%
R6 R7 R42 R43: library part CMP-0022235-5, "RES, 249, 1%, 0.1 W, AEC-Q200 Grade 0, 0603", Manufacturer=Vishay-Dale, Power_W=100mW, Supplier Part Number 1=541-249HCT-ND, TempCo="100 ppm/C", Tolerance_%=1%, Value2=0.1W, Value_Code=249R, ValueDisplayed=249
R8 R9 R23 R24: library part CMP-0021998-4, "RES, 10.0 k, 1%, 0.1 W, AEC-Q200 Grade 0, 0603", Manufacturer=Vishay-Dale, Power_W=100mW, Supplier Part Number 1=541-10.0KHCT-ND, TempCo="100 ppm/C", Tolerance_%=1%, Value2=0.1W, Value_Code=10k0, ValueDisplayed=10.0k
R12: library part CMP-0022188-4, "RES, 1.54, 1%, 0.1 W, AEC-Q200 Grade 0, 0603", Manufacturer=Vishay-Dale, Power_W=100mW, Supplier Part Number 1=541-1.54HHCT-ND, TempCo="100 ppm/C", Tolerance_%=1%, Value2=0.1W, Value_Code=1R54, ValueDisplayed=1.54
R14: library part CMP-0025727-4, "RES, 18 k, 5%, 0.1 W, AEC-Q200 Grade 0, 0603", Manufacturer=Vishay-Dale, Power_W=100mW, Supplier Part Number 1=541-18KGCT-ND, TempCo="200 ppm/C", Tolerance_%=5%, Value2=0.1W, Value_Code=18k0, ValueDisplayed=18k
R17: library part CMP-0022414-4, "RES, 41.2 k, 1%, 0.1 W, AEC-Q200 Grade 0, 0603", Manufacturer=Vishay-Dale, Power_W=100mW, Supplier Part Number 1=541-41.2KHCT-ND, TempCo="100 ppm/C", Tolerance_%=1%, Value2=0.1W, Value_Code=41k2, ValueDisplayed=41.2k
R18 R34: library part CMP-0022204-4, "RES, 20.0 k, 1%, 0.1 W, AEC-Q200 Grade 0, 0603", Manufacturer=Vishay-Dale, Power_W=100mW, Supplier Part Number 1=541-20.0KHCT-ND, TempCo="100 ppm/C", Tolerance_%=1%, Value2=0.1W, Value_Code=20k0, ValueDisplayed=20.0k
R19 R21: library part CMP-0022503-4, "RES, 57.6 k, 1%, 0.1 W, AEC-Q200 Grade 0, 0603", Manufacturer=Vishay-Dale, Power_W=100mW, Supplier Part Number 1=541-57.6KHCT-ND, TempCo="100 ppm/C", Tolerance_%=1%, Value2=0.1W, Value_Code=57k6, ValueDisplayed=57.6k
R20: library part CMP-0022651-4, "RES, 90.9 k, 1%, 0.1 W, AEC-Q200 Grade 0, 0603", Manufacturer=Vishay-Dale, Power_W=100mW, Supplier Part Number 1=541-90.9KHCT-ND, TempCo="100 ppm/C", Tolerance_%=1%, Value2=0.1W, Value_Code=90k9, ValueDisplayed=90.9k
R22 R25 R26 R27 R28 R29: library part CMP-0021990-4, "RES, 100 k, 1%, 0.1 W, AEC-Q200 Grade 0, 0603", Manufacturer=Vishay-Dale, Power_W=100mW, Supplier Part Number 1=541-100KHCT-ND, TempCo="100 ppm/C", Tolerance_%=1%, Value2=0.1W, Value_Code=100k
R30 R31 R32 R33: library part CMP-0025729-4, "RES, 1.0 k, 5%, 0.1 W, AEC-Q200 Grade 0, 0603", Manufacturer=Vishay-Dale, Power_W=100mW, Supplier Part Number 1=541-1.0KGCT-ND, TempCo="200 ppm/C", Tolerance_%=5%, Value2=0.1W, Value_Code=1k00, ValueDisplayed=1.0k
